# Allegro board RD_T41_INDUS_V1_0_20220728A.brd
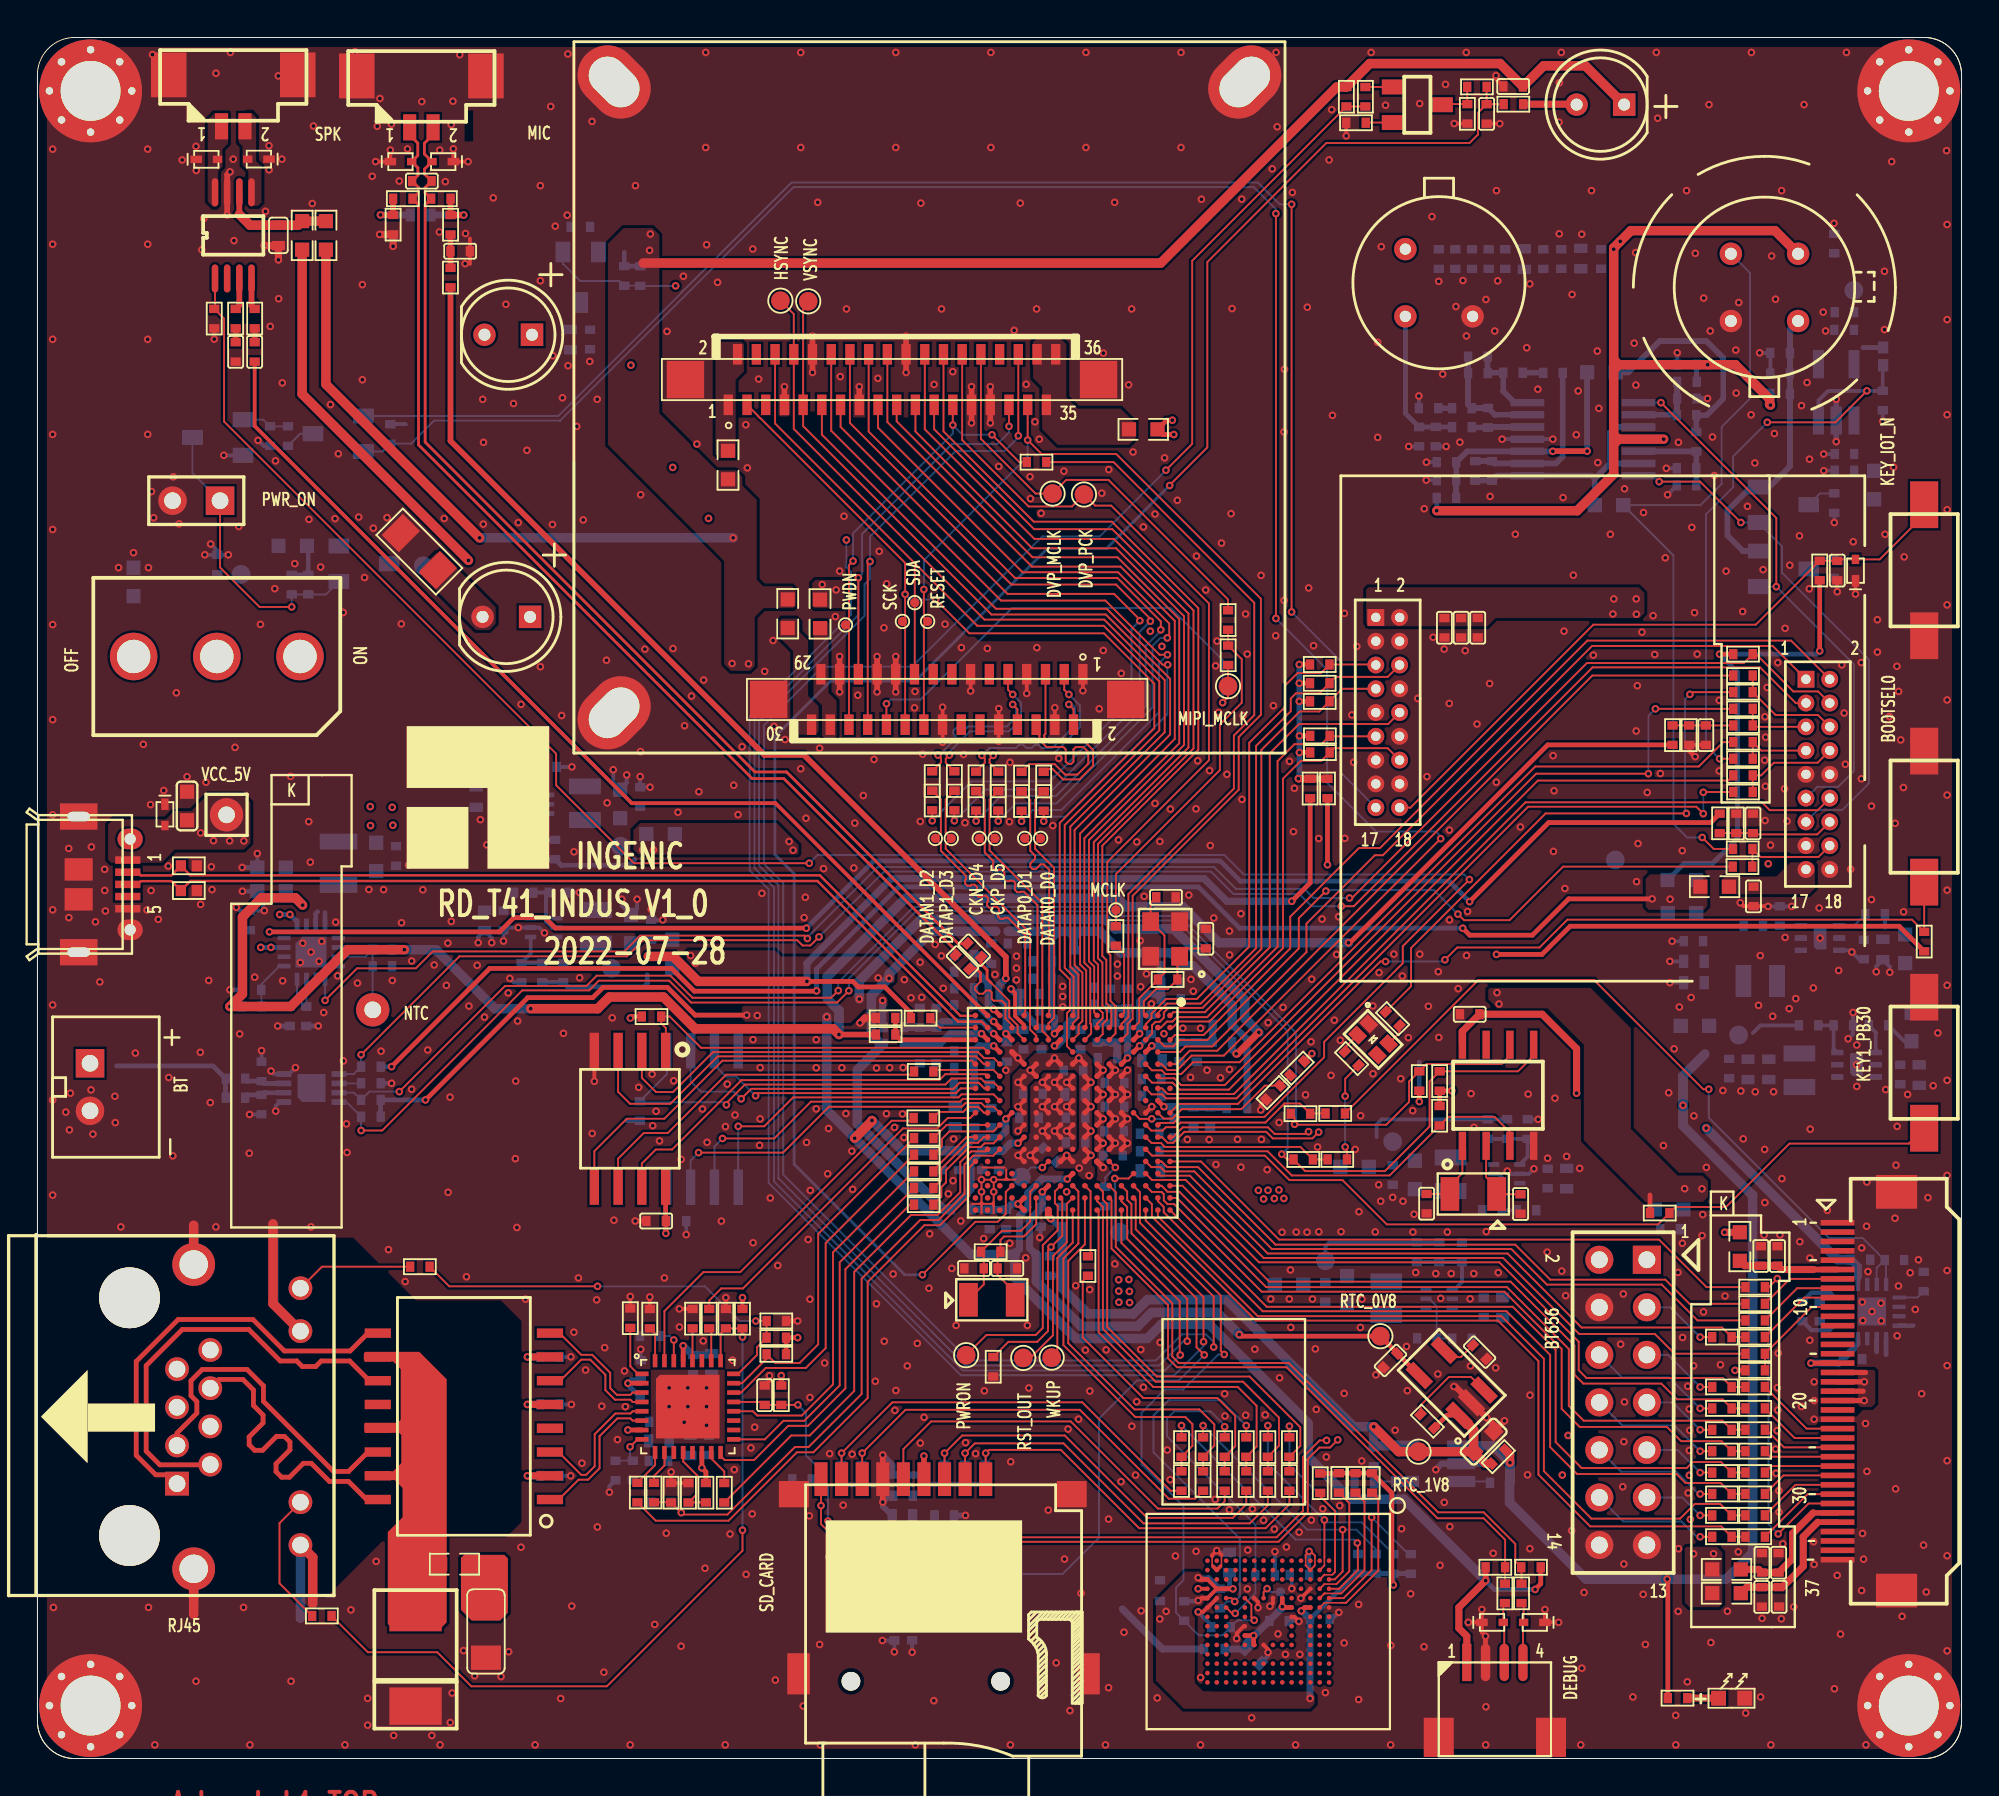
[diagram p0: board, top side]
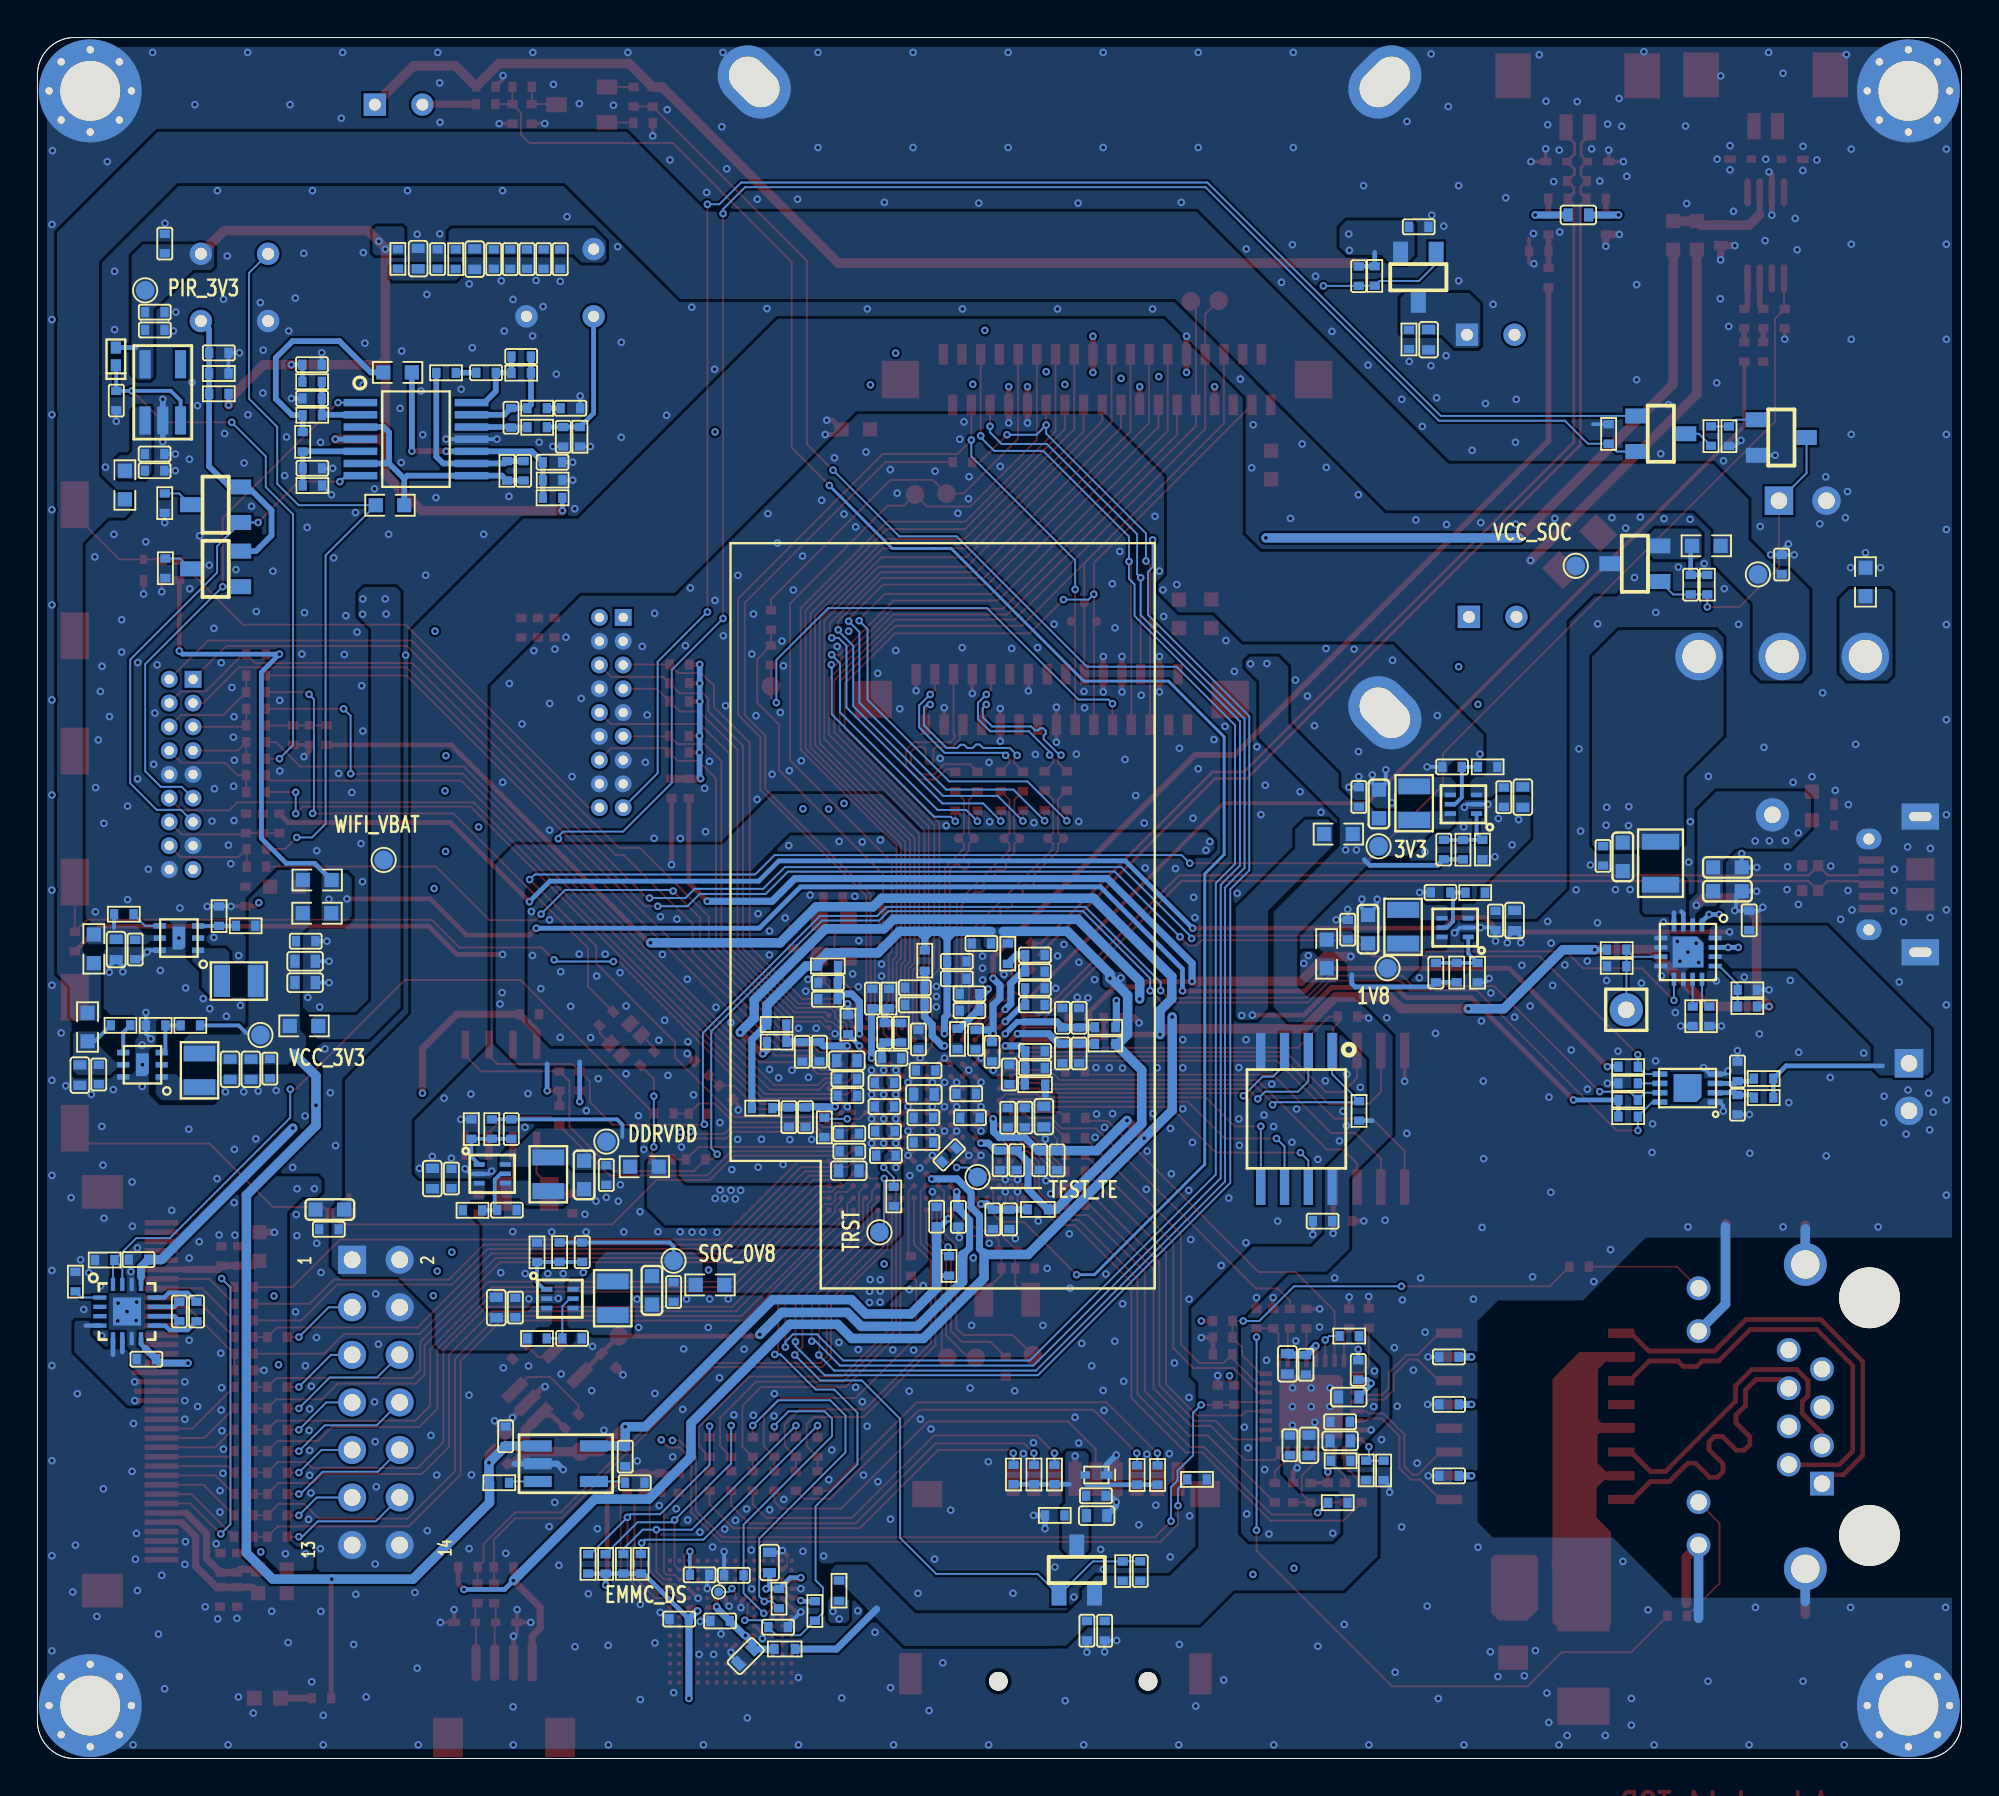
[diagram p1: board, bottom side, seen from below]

Outline 102.82 x 91.95 mm; copper layers: TOP, L2_GND, L3_PWR, BOTTOM. Coordinates in mm from the lower left corner of the outline.
Outline path: 0,89.95 0,2 ; 0,89.95 arc(0.59,91.36) 2,91.95 ; 0,89.95 0,2 ; 0,2 arc(0.59,0.59) 2,0 ; 0,2 arc(0.59,0.59) 2,0 ; 2,91.95 100.82,91.95 ; 2,91.95 100.82,91.95 ; 100.82,91.95 arc(102.24,91.36) 102.82,89.95 ; 100.82,91.95 arc(102.24,91.36) 102.82,89.95 ; 2,0 100.82,0 ; 2,0 100.82,0 ; 100.82,0 arc(102.24,0.59) 102.82,2 ; 100.82,0 arc(102.24,0.59) 102.82,2 ; 102.82,89.95 102.82,2 ; 102.82,89.95 102.82,2

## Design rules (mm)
net group CSI_CLKN_DVP_D4: nets CSI_CLKN_DVP_D4 MIPI_RX_2LANE_CLKN0
net group CSI_CLKP_DVP_D5: nets CSI_CLKP_DVP_D5 MIPI_RX_2LANE_CLKP0
net group CSI_DATAN0_DVP_D0: nets CSI_DATAN0_DVP_D0 MIPI_RX_2LANE_DN0
net group CSI_DATAN1_DVP_D2: nets CSI_DATAN1_DVP_D2 MIPI_RX_2LANE_DN1
net group CSI_DATAP0_DVP_D1: nets CSI_DATAP0_DVP_D1 MIPI_RX_2LANE_DP0
net group CSI_DATAP1_DVP_D3: nets CSI_DATAP1_DVP_D3 MIPI_RX_2LANE_DP1
net group MDI_RX: nets RX_N1 RX_P1
net group MDI_TX: nets TX_N0 TX_P0
net group MICNL: nets MICNL N16981743
net group MICPL: nets MICPL N16981740
net group RJ45_RX: nets RX+ RX-
net group RJ45_TX: nets TX+ TX-
net group USB: nets USB_DM0 USB_DP0
net group POWER: nets ADC_AVDD CODEC_AVDD CSI_VCC08 CSI_VCC18 DDR_VREF DDRPLL_VCCA EMMC_3V3 MICBIAS N16981952 PLL_AVDD18 RTC_0V8 RTC_1V8 SLCD_IOVDD SLCD_LEDA USB_AVD08 USB_AVD18 USB_AVD33 USB_VBUS VCM VOUT
nets with their own width: min track width 0.203; nets GND VCC_3V3

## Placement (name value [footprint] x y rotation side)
BT1  CON2 2.54mm LC  [CON2-2D54-LC]  2.81 35.87 270 top
C1  1uF/10V  [C0402]  9.61 63.79 90 bottom
C2  22uF/10V-0603  [C0603]  8 50.89 90 top
C3  22uF/10V-0603  [C0603]  18.11 48.17 270 bottom
C4  10nF/6.3V  [C0402]  19.16 48.22 270 bottom
C5  100nF/10V  [C0402]  91.67 49.96 90 top
C6  10uF/10V-0603  [C0603]  12.51 47.61 180 bottom
C7  10uF/10V-0603  [C0603]  12.51 46.34 180 bottom
C8  1uF/10V  [C0402]  11.35 44.78 90 bottom
C9  100nF/10V  [C0402]  89.16 54.67 270 top
C10  10uF/6.3V  [C0402_E]  98.62 43.22 270 bottom
C11  100nF/10V  [C0402]  97.6 43.22 270 bottom
C12  10uF/6.3V  [C0402_E]  88.52 42.59 180 bottom
C13  100nF/10V  [C0402]  88.49 43.67 180 bottom
C14  10uF/6.3V  [C0402_E]  88.52 41.45 180 bottom
C15  100nF/10V  [C0402]  14.48 62.71 270 bottom
C16  10uF/6.3V  [C0402_E]  23.45 51.36 270 bottom
C17  100nF/10V  [C0402]  24.46 51.36 270 bottom
C18  22uF/10V-0603  [C0603]  31.14 51 90 bottom
C19  100nF/10V  [C0402]  32.21 51.37 90 bottom
C20  10uF/6.3V  [C0402_E]  23.89 44.77 270 bottom
C21  100nF/10V  [C0402]  24.91 44.77 270 bottom
C22  22uF/10V-0603  [C0603]  31.72 44.31 90 bottom
C23  100nF/10V  [C0402]  32.8 44.28 90 bottom
C24  22pF/50V  [C0402]  27.67 48.56 90 bottom
C25  22pF/50V  [C0402]  28.09 41.99 90 bottom
C26  10uF/6.3V  [C0402_E]  81.72 30.99 90 bottom
C27  100nF/10V  [C0402]  80.7 30.99 90 bottom
C28  22uF/10V-0603  [C0603]  73.61 31.18 270 bottom
C29  100nF/10V  [C0402]  72.42 31.17 270 bottom
C30  10uF/6.3V  [C0402_E]  78.3 24.1 90 bottom
C31  100nF/10V  [C0402]  77.29 24.1 90 bottom
C32  22uF/10V-0603  [C0603]  69.99 25.01 270 bottom
C33  100nF/10V  [C0402]  68.83 24.92 270 bottom
C34  22pF/50V  [C0402]  77.5 33.63 270 bottom
C35  22pF/50V  [C0402]  73.71 27.05 270 bottom
C36  1uF/10V  [C0402]  11.98 34.93 270 bottom
C37  10uF/6.3V  [C0402_E]  59.47 31.4 0 bottom
C38  100nF/6.3V  [C0402]  59.44 33.38 0 bottom
C39  100nF/6.3V  [C0402]  59.44 32.44 0 bottom
C40  100nF/6.3V  [C0402]  59.54 35.41 0 bottom
C41  10nF/6.3V  [C0402]  59.54 36.3 0 bottom
C42  100nF/6.3V  [C0402]  57.55 38.78 90 bottom
C43  100nF/6.3V  [C0402]  58.21 40.6 90 bottom
C44  1uF/6.3V  [C0402]  57.18 37.42 180 bottom
C45  1uF/10V  [C0402]  11.98 36.71 90 bottom
C46  10uF/6.3V  [C0402_E]  49.04 34.29 270 bottom
C47  10uF/6.3V  [C0402_E]  55.45 35.48 180 bottom
C48  100nF/6.3V  [C0402]  54.1 32.25 135 bottom
C49  100nF/6.3V  [C0402]  55.48 34.24 180 bottom
C50  100nF/6.3V  [C0402]  55.74 38.42 90 bottom
C51  100nF/6.3V  [C0402]  52.99 34.24 0 bottom
C52  100nF/6.3V  [C0402]  50.89 36.55 90 bottom
C53  100nF/6.3V  [C0402]  50.07 34.25 270 bottom
C54  10nF/6.3V  [C0402]  55.48 32.92 180 bottom
C55  10nF/6.3V  [C0402]  55.36 36.76 180 bottom
C56  10nF/6.3V  [C0402]  53.19 35.52 0 bottom
C57  10nF/6.3V  [C0402]  50.97 34.24 270 bottom
C58  10uF/6.3V  [C0402_E]  59.57 37.28 0 bottom
C59  1uF/6.3V  [C0402]  60.58 41.45 0 bottom
C60  100nF/6.3V  [C0402]  60.58 40.56 0 bottom
C61  100nF/25V  [C0402]  49.52 42.93 180 bottom
C62  4.7uF/6.3V  [C0402]  49.52 42.04 180 bottom
C63  4.7uF/6.3V  [C0402]  52.38 43.54 0 bottom
C64  100nF/25V  [C0402]  50.06 43.18 135 top
C65  100nF/25V  [C0402]  49.44 42.56 135 top
C66  12pF/50V  [C0402]  62.44 43.8 270 top
C67  12pF/50V  [C0402]  60.31 46.01 180 top
C68  4.7uF/6.3V  [C0402]  49.52 40.26 180 bottom
C69  100nF/25V  [C0402]  49.52 41.15 180 bottom
C70  100nF/25V  [C0402]  33.06 28.72 0 top
C71  18pF/50V  [C0402]  51.83 26.19 180 top
C72  18pF/50V  [C0402]  50.05 26.19 0 top
C73  1uF/6.3V  [C0402]  50.88 28.8 270 bottom
C74  100nF/6.3V  [C0402]  51.77 28.8 270 bottom
C75  3.3nF/50V  [C0402]  10.59 75.15 270 top
C76  3.3nF/50V  [C0402]  11.61 75.15 270 top
C77  10uF/6.3V  [C0402_E]  12.88 81.37 270 top
C78  100pF/50V  [C0402]  20.54 84.27 0 top
C79  10uF/6.3V  [C0402_E]  20.48 82.46 0 bottom
C80  4.7uF/6.3V  [C0402]  46.74 6.83 270 bottom
C81  100nF/25V  [C0402]  45.79 6.83 270 bottom
C82  100nF/6.3V  [C0402]  43.89 10.02 90 bottom
C83  10uF/6.3V  [C0402_E]  46.22 12.98 180 bottom
C84  100nF/25V  [C0402]  46.26 14.04 180 bottom
C85  4.7uF/6.3V  [C0402]  22.59 80.53 0 top
C86  1uF/6.3V  [C0402]  77.8 17.22 90 bottom
C87  10uF/6.3V  [C0402_E]  64.97 5.47 315 bottom
C88  100nF/6.3V  [C0402]  66.35 7.35 0 bottom
C89  10uF/6.3V  [C0402_E]  63.7 10.48 90 bottom
C90  100nF/6.3V  [C0402]  68.53 7.45 0 bottom
C91  8.2pF/50V  [C0402]  65.61 9.79 0 bottom
C92  1uF/6.3V  [C0402]  63.25 7.02 180 bottom
C93  1uF/6.3V  [C0402]  67.44 9.82 180 bottom
C94  1uF/6.3V  [C0402]  71.41 16.13 270 bottom
C95  100nF/6.3V  [C0402]  96.18 63.47 90 top
C96  100nF/10V  [C0402]  27.23 52.98 0 bottom
C97  10nF/6.3V  [C0402]  70.91 14.74 180 bottom
C98  10uF/6.3V-0603  [C0603]  77.29 16.93 45 top
C99  1uF/6.3V  [C0402]  72.3 21.27 225 top
C100  10nF/6.3V  [C0402]  77.07 21.72 315 top
C101  100nF/6.3V  [C0402]  29.01 81.83 180 bottom
C102  100nF/6.3V  [C0402]  32.22 79.2 270 bottom
C103  1uF/6.3V  [C0402]  92.99 26.85 90 top
C104  100nF/6.3V  [C0402]  92.1 26.85 90 top
C105  1uF/6.3V  [C0402]  92.16 10.46 90 top
C106  100nF/6.3V  [C0402]  93.05 10.46 90 top
C107  10uF/6.3V  [C0402_E]  28.48 75.8 270 bottom
C108  100nF/10V  [C0402]  74.25 22.45 180 bottom
C109  10uF/10V-0603  [C0603]  87.2 29.33 0 bottom
C110  1uF/10V  [C0402]  87.25 28.27 0 bottom
C111  100nF/6.3V  [C0402]  76.97 60.41 270 top
C112  100nF/6.3V  [C0402]  76.08 60.41 270 top
C113  4.7uF/6.3V  [C0402]  75.19 60.41 270 top
C114  100nF/25V  [C0402]  91.71 46.06 270 top
C116  10uF/6.3V  [C0402_E]  34.88 16.74 90 bottom
C117  100nF/6.3V  [C0402]  35.89 16.74 90 bottom
C118  10uF/6.3V  [C0402_E]  32.75 19.31 0 bottom
C119  100nF/6.3V  [C0402]  32.24 20.76 90 bottom
C120  100nF/6.3V  [C0402]  78.86 89.33 180 top
C121  100nF/10V  [C0402]  96.56 69.69 180 bottom
C122  1uF/10V  [C0402]  96.56 68.8 180 bottom
C123  1uF/10V  [C0402]  96.55 76.32 180 bottom
C124  100nF/10V  [C0402]  96.56 77.27 180 bottom
C125  100nF/6.3V  [C0402]  77.44 87.86 270 top
C126  100nF/10V  [C0402]  98.61 72.55 270 bottom
C127  100nF/6.3V  [C0402]  88.15 74.46 180 bottom
C128  10uF/6.3V  [C0402_E]  82.48 80.13 90 bottom
C129  100nF/6.3V  [C0402]  57.56 36.1 180 bottom
C130  100nF/6.3V  [C0402]  57.49 32.21 180 bottom
C131  100nF/6.3V  [C0402]  57.54 33.51 180 bottom
C132  10nF/6.3V  [C0402]  57.56 34.83 180 bottom
C133  1uF/6.3V  [C0402]  61.78 34.27 270 bottom
C134  100nF/6.3V  [C0402]  62.67 34.27 270 bottom
C135  1uF/6.3V  [C0402]  49.51 36.89 180 bottom
C136  100nF/6.3V  [C0402]  49.51 37.78 180 bottom
C137  1uF/6.3V  [C0402]  47.16 37.67 270 bottom
C138  100nF/6.3V  [C0402]  48.05 37.67 270 bottom
C139  1uF/6.3V  [C0402]  47.16 39.58 90 bottom
C140  100nF/6.3V  [C0402]  48.05 39.58 90 bottom
C141  4.7uF/6.3V  [C0402]  51.81 37.76 270 bottom
C142  100nF/6.3V  [C0402]  52.69 38.41 270 bottom
C143  100nF/6.3V  [C0402]  53.61 28.94 270 bottom
C144  1uF/6.3V  [C0402]  55.94 40.27 0 bottom
C145  100nF/6.3V  [C0402]  55.94 41.18 0 bottom
C146  1uF/6.3V  [C0402]  53.02 39.96 0 bottom
C147  100nF/6.3V  [C0402]  53.02 40.85 0 bottom
C148  100nF/6.3V  [C0402]  34.15 28.71 180 bottom
C149  10uF/6.3V  [C0402_E]  36.03 21.09 270 bottom
C150  100nF/6.3V  [C0402]  35.04 21.04 270 bottom
C151  100nF/6.3V  [C0402]  38.86 19.41 90 top
C152  10uF/6.3V  [C0402_E]  33.21 16.97 0 bottom
C153  100nF/6.3V  [C0402]  33.21 17.99 0 bottom
C154  100nF/6.3V  [C0402]  27.39 15.1 180 bottom
C155  100nF/6.3V  [C0402]  27.39 18.92 180 bottom
C156  100nF/6.3V  [C0402]  27.4 21.46 180 bottom
C157  1nF/2KV-1206  [C1206]  23.97 6.79 90 top
C158  18pF/50V  [C0402]  74.24 29.65 90 top
C159  18pF/50V  [C0402]  79.26 29.63 90 top
C164  10uF/6.3V  [C0402_E]  100.56 36.51 270 bottom
C165  100nF/10V  [C0402]  99.55 36.54 270 bottom
C166  10uF/6.3V  [C0402_E]  91.41 36.82 270 bottom
C167  100nF/10V  [C0402]  90.4 36.86 270 bottom
C168  10uF/6.3V  [C0402_E]  92.53 36.82 270 bottom
C169  100nF/6.3V  [C0402]  54.77 28.95 90 bottom
C170  1uF/6.3V  [C0402]  48.34 31.96 270 bottom
C171  100nF/6.3V  [C0402]  49.26 31.96 270 bottom
C172  1uF/6.3V  [C0402]  61.03 37.76 270 bottom
C173  100nF/6.3V  [C0402]  61.95 37.75 270 bottom
C174  1uF/6.3V  [C0402]  53.69 42.59 180 bottom
C175  100nF/6.3V  [C0402]  53.69 41.66 180 bottom
C176  1uF/6.3V  [C0402]  50.49 31.96 270 bottom
C177  100nF/6.3V  [C0402]  51.38 31.96 270 bottom
C179  1uF/6.3V  [C0402]  93.07 8.64 270 top
C180  100nF/6.3V  [C0402]  92.15 8.64 270 top
C181  100nF/6.3V  [C0402]  76.54 39.76 180 top
C182  470nF/16V  [C0402]  94.32 23.88 270 bottom
C183  470nF/16V  [C0402]  95.24 23.89 270 bottom
C184  1uF/16V  [C0402]  97.42 26.66 180 bottom
C185  1uF/16V  [C0402]  97 21.33 180 bottom
C187  100nF/6.3V  [C0402]  81.44 80.11 90 bottom
C188  10uF/6.3V  [C0402_E]  79.46 80.1 270 bottom
C189  1uF/6.3V  [C0402]  78.44 80.11 270 bottom
C190  470nF/25V  [C0402]  77.55 80.11 270 bottom
C191  10nF/25V  [C0402]  76.66 80.11 270 bottom
C192  1nF/50V  [C0402]  75.78 80.11 270 bottom
C193  220pF/50V  [C0402]  74.89 80.11 270 bottom
C194  100nF/6.3V  [C0402]  88.15 72.66 0 bottom
C195  10nF/6.3V  [C0402]  76.84 68.8 270 bottom
C196  100nF/6.3V  [C0402]  96.02 80.93 90 bottom
C197  4.7uF/6.3V  [C0402]  78.85 74.04 0 bottom
C198  100nF/6.3V  [C0402]  74.72 70.62 270 bottom
C199  10nF/6.3V  [C0402]  77.52 71.63 90 bottom
C200  10nF/6.3V  [C0402]  76.97 74.91 0 bottom
C201  100nF/6.3V  [C0402]  75.3 69.26 180 bottom
C202  4.7uF/6.3V  [C0402]  74.34 72.14 180 bottom
C203  100nF/6.3V  [C0402]  88.13 68.93 180 bottom
C204  100nF/6.3V  [C0402]  93.13 75.1 180 bottom
C205  100nF/10V  [C0402]  27.84 46.27 0 bottom
C206  100nF/10V  [C0402]  77.74 29.3 180 bottom
D1  LXES1UTAA1-157  [DFN1006]  8.09 46.37 0 top
D2  LXES1UTAA1-157  [DFN1006]  8.09 47.69 0 top
D3  ESD5451X  [ESD0402]  6.81 50.45 270 top
D4  ESD5451X  [ESD0402]  80.02 7.28 180 top
D5  ESD5451X  [ESD0402]  77.73 7.28 0 top
D6  ESD5451X  [ESD0402]  11.84 85.45 180 top
D7  ESD5451X  [ESD0402]  9.02 85.44 0 top
D8  ESD5451X  [ESD0402]  46.23 15.15 0 bottom
D9  ESD5451X  [ESD0402]  21.69 85.31 180 top
D10  ESD5451X  [ESD0402]  97.16 63.46 90 top
D11  LED RGB CC  [D0603_LED3_CC]  71.38 38.42 135 top
D12  BAT54C  [SOT23]  16.07 70.78 270 bottom
D13  LED Red  [D0603_LED]  90.54 3.22 0 top
D14  940nm IRLED  [DIP2_2D54_LED]  25.16 76.06 180 top
D15  ESD5451X  [ESD0402]  19.4 85.31 0 top
D16  940nm IRLED  [DIP2_2D54_LED]  25.06 60.99 180 top
D17  P3100SC  [SMB]  20.21 5.3 90 top
D18  RB521CS-30  [SOD923_RB521CS-30]  98.63 74.9 270 bottom
FB1  220ohm/1.4A  [FB0402]  62.89 5.85 0 bottom
FB2  1000ohm/250mA  [FB0402]  64.1 34.75 0 bottom
FB3  1000ohm/250mA  [FB0402]  60.58 42.34 0 bottom
FB4  1000ohm/250mA  [FB0402]  49.51 36.01 0 bottom
FB5  1000ohm/250mA  [FB0402]  45.76 38.18 0 bottom
FB6  1000ohm/250mA  [FB0402]  45.76 39.07 0 bottom
FB7  1000ohm/250mA  [FB0402]  49.36 29.34 0 bottom
FB8  1000ohm/250mA  [FB0402]  50.97 43 270 bottom
FB9  1000ohm/250mA  [FB0402]  53.66 38.45 270 bottom
FB10  1000ohm/250mA  [FB0402]  55.41 42.63 90 bottom
FB11  220ohm/1.4A  [FB0402]  59.99 8.97 270 bottom
H1  MHOBL  [MHOLE_3D0X2D0]  30.82 89.57 270 top
H2  MHOBL  [MHOLE_3D0X2D0]  64.52 89.57 0 top
H3  MHOBL  [MHOLE_3D0X2D0]  30.82 55.87 0 top
J1  SW3 4.45mm  [PSW_3P]  9.59 58.88 270 top
J2  MICRO USB  [MICROUSB_B_NJ5P]  4.83 46.7 90 top
J3  HEADER2 2.54mm  [SIP2M_2D54]  8.49 67.2 180 top
J4  CON4 1.0mm WT  [CON4-1D0-WT]  77.89 2.64 0 top
J5  CON2 1.25mm LT  [CON2-1D25-LT]  10.47 89.4 180 top
J6  MICROSD_TF  [TFCARD]  48.42 14.73 0 top
J7  CON2 1.25mm LT  [CON2-1D25-LT]  20.52 89.35 180 top
J9  HEADER18 1.27mm Male  [HEADER9X2M_1D27]  72.16 55.88 90 top
J10  CON36 0.5mm LT  [FPC-CON36-0D5-LT]  45.67 73.67 0 top
J11  CON30 0.5mm LT  [FPC-CON30-0D5-LT]  48.62 56.58 180 top
J12  HEADER14 2.54mm MALE  [HEADER7X2M_2D54]  84.74 19.03 270 top
J13  RJ45 With Led  [RJ45-LED-1A]  -0.21 18.27 270 top
J14  HEADER18 1.27mm Male  [HEADER9X2M_1D27]  95.15 52.58 90 top
J15  CON37 0.5mm QCHX  [LCD_CON37_0D5_WTXG_MTF28]  99.2 19.63 90 top
L1  2.2uH/2.2A-2520  [L2520]  16.09 47.83 90 bottom
L2  2.2uH/1.5A-2016  [L2016]  92.06 41.54 0 bottom
L3  1uH/2.7A  [L2016]  29.25 51.04 90 bottom
L4  1uH/2.7A  [L2016]  29.85 44.44 90 bottom
L5  1uH/2.7A  [L2016]  75.52 31.22 270 bottom
L6  1uH/2.7A  [L2016]  72.08 24.59 270 bottom
L8  2.2uH/1.5A-2016  [L2016]  94.16 36.77 270 bottom
NOREF  -  []  4.32 233.9 0 top
NOREF#2  -  []  -98.17 -124.02 0 top
NOREF#3  -  []  85.84 253.93 0 top
NOREF#4  -  []  0 89.95 0 top
NOREF#5  -  []  2 0 90 top
NOREF#6  -  []  23.29 51.09 0 top
Q1  WPM3401  [SOT23]  17.46 63.83 90 bottom
Q2  MMBT3904  [SOT23]  9.63 70.58 270 bottom
Q3  WPM3401  [SOT23]  47.28 10.07 180 bottom
Q4  XYC-PTJZ5E550BC-IC-C  [PD2_2D54]  83.52 88.36 0 top
Q5  WNM2016  [SOT23]  73.74 88.35 270 top
Q6  WPM3401  [SOT23]  93.3 63.56 90 bottom
Q7  WPM3401  [SOT23]  93.3 66.99 90 bottom
Q8  WPM3401  [SOT23]  29.03 79.14 0 bottom
R1  300R-0603  [R0603]  5.13 62.86 270 bottom
R2  750K/1%  [R0402]  89.9 49.96 90 top
R3  499K/1%  [R0402]  90.79 49.96 270 top
R4  10K  [R0402]  11.45 40.18 180 bottom
R5  10K  [R0402]  11.45 41.07 180 bottom
R6  560R/1%  [R0402]  14.37 39.66 90 bottom
R7  2K/1%  [R0402]  13.48 39.66 90 bottom
R8  100K  [R0402]  91.14 59 180 top
R9  10K  [R0402]  18.43 43.21 0 bottom
R10  100K  [R0402]  87.38 54.67 270 top
R11  100K  [R0402]  18.43 42.32 180 bottom
R12  200K/1%  [R0402]  88.27 54.67 90 top
R13  0R-0603  [R0603]  88.58 39.14 0 bottom
R14  0R-0603  [R0603]  99.81 43.26 90 bottom
R15  100K  [R0402]  98.21 45.11 0 bottom
R16  1M/1%  [R0402]  91.7 44.49 180 bottom
R17  499K/1%  [R0402]  93.12 45.01 270 bottom
R18  0R-0603  [R0603]  13.64 64.79 0 bottom
R19  0R-0603  [R0603]  33.3 49.39 180 bottom
R20  0R-0603  [R0603]  33.93 42.99 90 bottom
R21  100K  [R0402]  13.59 62.71 270 bottom
R22  100K  [R0402]  25.33 52.98 0 bottom
R23  1M/1%  [R0402]  26.98 41.99 270 bottom
R24  10K/1%  [R0402]  45.33 38.68 180 top
R25  1M/1%  [R0402]  26.65 48.56 270 bottom
R26  100K  [R0402]  25.99 46.26 0 bottom
R27  15K/1%  [R0402]  45.33 39.57 180 top
R28  221K/1%  [R0402]  25.6 48.56 90 bottom
R29  499K/1%  [R0402]  25.87 41.99 90 bottom
R30  0R-0603  [R0603]  70.39 31.62 0 bottom
R31  0R-0603  [R0603]  66.88 25.3 0 bottom
R32  100K  [R0402]  79.58 29.29 180 bottom
R33  750K/1%  [R0402]  78.54 33.63 90 bottom
R34  100K  [R0402]  76.13 22.44 180 bottom
R35  249K/1%  [R0402]  74.92 27.05 90 bottom
R36  499K/1%  [R0402]  79.64 33.63 270 bottom
R37  750K/1%  [R0402]  76.13 27.04 270 bottom
R38  33R  [R0402]  57.63 43.94 270 top
R39  33R  [R0402]  56.14 26.31 270 top
R40  10K  [R0402]  17.82 34.3 180 bottom
R41  1M  [R0402]  60.4 41.62 0 top
R42  10K  [R0402]  77.91 10.22 180 top
R43  33R  [R0402]  47.36 36.7 0 top
R44  100K  [R0402]  32.82 39.64 180 top
R45  10K  [R0402]  79.82 10.22 0 top
R46  10K  [R0402]  17.82 35.19 180 bottom
R47  100K  [R0402]  17.82 36.96 180 bottom
R48  33R  [R0402]  78.42 8.82 90 top
R49  470R  [R0402]  10.58 35.31 180 bottom
R50  100R  [R0402]  10.58 36.33 180 bottom
R51  33R  [R0402]  79.31 8.82 90 top
R52  1M  [R0402]  50.94 27.07 0 top
R53  10K  [R0402]  17.82 36.07 0 bottom
R54  0R-0603  [R0603]  87.87 46.93 0 bottom
R55  1K  [R0402]  47.2 39.55 180 top
R56  0R-0603  [R0603]  14.15 81.37 270 top
R57  0R-0603  [R0603]  15.42 81.37 270 top
R58  100K  [R0402]  9.45 76.93 270 top
R59  68K/1%  [R0402]  10.59 76.93 270 top
R60  68K/1%  [R0402]  11.61 76.93 270 top
R61  100K  [R0402]  48.48 15.17 90 bottom
R62  100K  [R0402]  44.06 15.15 90 bottom
R63  100K  [R0402]  42.97 15.15 90 bottom
R64  100K  [R0402]  50.66 15.17 90 bottom
R65  100K  [R0402]  49.57 15.17 90 bottom
R66  100K  [R0402]  44.83 10.01 90 bottom
R67  1.1K  [R0402]  19.01 81.95 270 top
R68  100K  [R0402]  48.46 12.99 0 bottom
R69  1.1K  [R0402]  19.53 83.33 180 top
R70  10K  [R0402]  71.51 10.41 90 bottom
R71  10K  [R0402]  70.57 10.41 90 bottom
R72  10K  [R0402]  73.4 10.4 90 bottom
R73  10K  [R0402]  72.46 10.4 90 bottom
R74  10K  [R0402]  68.55 14.71 270 top
R75  10K  [R0402]  69.55 14.72 270 top
R76  10K  [R0402]  70.44 14.72 270 top
R77  10K  [R0402]  71.32 14.72 270 top
R78  10K  [R0402]  63.2 8.55 270 bottom
R79  100K  [R0402]  61.28 7.88 90 bottom
R80  1.1K  [R0402]  21.56 83.33 180 top
R81  1.1K  [R0402]  22.08 81.94 90 top
R82  0R  [R0402]  64.6 14.83 270 top
R83  0R  [R0402]  22.07 79.12 270 top
R84  0R  [R0402]  64.6 16.64 90 top
R85  0R  [R0402]  63.44 14.83 270 top
R86  0R  [R0402]  63.44 16.64 90 top
R87  0R  [R0402]  62.29 14.83 270 top
R88  10K  [R0402]  40.86 14.91 180 bottom
R89  100K  [R0402]  86.69 29.14 180 top
R90  100K  [R0402]  95.24 63.47 90 top
R91  1M/1%  [R0402]  96.51 39.17 0 bottom
R92  10K/1%  [R0402]  78.87 88.38 0 top
R93  0R-0603  [R0603]  87.88 45.16 0 bottom
R94  1K  [R0402]  70.23 37.4 135 top
R95  1K  [R0402]  72.42 39.53 315 top
R96  620K/1%  [R0402]  94.65 39.17 180 bottom
R97  0R  [R0402]  78.07 16.13 225 top
R98  0R  [R0402]  68.94 51.82 270 top
R99  0R-0603  [R0603]  36.9 69.1 270 top
R100  0R  [R0402]  52.59 52.2 90 top
R101  0R  [R0402]  52.59 51.16 270 top
R102  0R  [R0402]  53.78 52.2 90 top
R103  0R  [R0402]  53.78 51.16 270 top
R104  0R  [R0402]  49 52.22 90 top
R105  0R  [R0402]  49 51.18 270 top
R106  0R  [R0402]  47.82 52.22 90 top
R107  0R  [R0402]  47.82 51.18 270 top
R108  0R  [R0402]  51.34 52.21 90 top
R109  0R  [R0402]  51.34 51.17 270 top
R110  0R  [R0402]  50.16 52.21 90 top
R111  0R-0603  [R0603]  98.15 68.04 90 bottom
R112  100K  [R0402]  69.95 88.78 90 top
R113  0R  [R0402]  76.93 89.31 180 top
R114  100R  [R0402]  70.96 88.78 270 top
R115  100K/1%  [R0402]  76.41 87.87 90 top
R116  240R/1%  [R0402]  57.06 30.03 90 bottom
R117  240R/1%  [R0402]  60.77 33.72 90 bottom
R118  10K/1%  [R0402]  56.66 38.78 270 bottom
R119  10K/1%  [R0402]  57.32 40.6 270 bottom
R120  33R  [R0402]  59.51 39.21 270 bottom
R121  1K  [R0402]  54.11 26.32 90 bottom
R122  1K  [R0402]  51.08 20.93 90 top
R123  100K  [R0402]  32.2 34.6 270 bottom
R124  0R  [R0402]  50.16 51.17 270 top
R125  0R  [R0402]  63.63 58.94 270 top
R126  0R  [R0402]  63.63 60.82 90 top
R127  0R-0603  [R0603]  59.1 71.01 0 top
R128  0R-0603  [R0603]  41.82 61.15 270 top
R129  0R-0603  [R0603]  40.09 61.16 270 top
R130  0R  [R0402]  91.8 19.85 0 top
R131  0R  [R0402]  62.29 16.64 90 top
R132  0R  [R0402]  61.14 14.83 270 top
R133  0R  [R0402]  61.14 16.64 90 top
R134  0R  [R0402]  66.9 14.83 270 top
R135  0R  [R0402]  66.9 16.64 90 top
R136  0R  [R0402]  65.75 14.83 270 top
R137  0R  [R0402]  65.75 16.64 90 top
R138  0R  [R0402]  63.32 38.28 180 bottom
R139  0R  [R0402]  68.01 51.82 270 top
R140  4.7K  [R0402]  74.94 36.2 270 top
R141  10K  [R0402]  78.14 14.74 180 bottom
R142  100K  [R0402]  74.28 18.03 135 top
R143  0R  [R0402]  53.39 69.26 0 top
R144  0R  [R0402]  90.02 19.85 180 top
R145  0R  [R0402]  91.8 18.71 0 top
R146  0R  [R0402]  90.02 18.71 180 top
R147  0R-0603  [R0603]  90.26 10.1 0 top
R148  0R-0603  [R0603]  90.26 8.83 0 top
R149  0R  [R0402]  91.8 17.57 0 top
R150  0R  [R0402]  90.02 17.56 180 top
R151  0R-0603  [R0603]  90.97 27.35 270 top
R152  4.7K  [R0402]  73.85 36.2 270 top
R153  10K  [R0402]  74.93 34.34 90 top
R154  0R  [R0402]  91.8 16.42 0 top
R155  0R  [R0402]  90.02 16.42 180 top
R156  0R  [R0402]  91.8 15.28 0 top
R157  0R  [R0402]  91.8 20.74 180 top
R158  0R  [R0402]  90.02 15.28 180 top
R159  10R/1%-1206  [R1206]  20.41 64.48 135 top
R160  0R  [R0402]  91.8 14.14 0 top
R161  0R  [R0402]  90.02 14.13 180 top
R162  0R  [R0402]  91.8 12.99 0 top
R163  0R  [R0402]  90.02 12.99 180 top
R164  0R  [R0402]  91.8 11.85 0 top
R165  10K  [R0402]  31.36 79.21 90 bottom
R166  0R  [R0402]  90.02 11.85 180 top
R167  100K  [R0402]  29.53 75.81 270 bottom
R168  0R  [R0402]  91.8 22.52 0 top
R169  0R  [R0402]  90.02 22.52 180 top
R170  0R  [R0402]  91.8 25.19 0 top
R171  0R  [R0402]  91.8 24.3 0 top
R172  0R  [R0402]  91.8 23.41 0 top
R173  0R-0603  [R0603]  100.15 39.08 270 bottom
R174  0R  [R0402]  91.8 21.63 0 top
R175  33R  [R0402]  47.34 34.22 180 top
R176  0R  [R0402]  47.36 31.37 180 top
R177  0R  [R0402]  47.36 32.26 180 top
R178  0R  [R0402]  47.36 33.15 180 top
R179  33R  [R0402]  47.36 29.59 180 top
R180  33R  [R0402]  47.36 30.48 180 top
R181  0R  [R0402]  69.46 32.01 180 top
R182  0R  [R0402]  67.64 32.01 0 top
R183  0R  [R0402]  69.35 34.46 180 top
R184  0R  [R0402]  67.5 34.45 0 top
R185  0R  [R0402]  63.32 39.21 180 bottom
R186  0R-0603  [R0603]  89.63 46.58 180 top
R187  0R  [R0402]  91.14 56.08 0 top
R188  0R  [R0402]  91.14 55.19 0 top
R189  1.5K  [R0402]  39.49 21.6 180 top
R190  33R  [R0402]  36.7 14.2 90 top
R191  33R  [R0402]  35.9 23.5 270 top
R192  10K  [R0402]  33.34 13.67 0 bottom
R193  10K  [R0402]  33.86 14.2 90 top
R194  2.49K/1%  [R0402]  31.68 23.53 90 top
R195  33R  [R0402]  32.06 14.21 90 top
R196  10K  [R0402]  31.82 15.39 90 bottom
R197  10K  [R0402]  30.89 15.39 270 bottom
R198  33R  [R0402]  32.95 14.21 90 top
R199  10K  [R0402]  35.72 14.2 270 top
R200  10K  [R0402]  34.79 14.2 90 top
R201  10K  [R0402]  35.01 23.5 270 top
R202  10K  [R0402]  39.49 22.49 180 top
R203  10K  [R0402]  39.49 23.38 0 top
R204  0R  [R0402]  32.73 23.5 270 top
R205  10K  [R0402]  37.68 23.5 270 top
R206  10K  [R0402]  36.79 23.5 90 top
R207  10K  [R0402]  39.75 19.41 270 top
R208  100K  [R0402]  98.38 39.17 0 bottom
R209  10K  [R0402]  32.72 22.57 180 bottom
R210  0R  [R0402]  33.18 15.91 0 bottom
R211  300R  [R0402]  20.44 26.28 0 top
R212  10K  [R0402]  99.23 26.63 0 bottom
R213  0R  [R0402]  91.14 52.52 0 top
R214  7.68K/1%  [R0402]  100.8 25.48 90 bottom
R215  0R  [R0402]  91.14 51.64 0 top
R217  300R  [R0402]  15.2 7.62 0 top
R218  0R  [R0402]  91.14 54.3 0 top
R220  0R  [R0402]  91.14 53.41 0 top
R221  75R/1%-0603  [R0603]  22.28 10.39 180 top
R223  0R  [R0402]  91.14 57.86 0 top
R225  0R  [R0402]  91.14 56.97 0 top
R226  27K/1%  [R0402]  70.46 87.39 0 top
R227  15M/1%  [R0402]  88.15 73.55 0 bottom
R228  20K/1%  [R0402]  83.56 80.11 270 bottom
R229  0R  [R0402]  91.12 47.65 0 top
R230  0R  [R0402]  91.13 48.59 0 top
R231  1M  [R0402]  13.39 70.65 270 bottom
R232  1M  [R0402]  12.43 70.65 90 bottom
R233  4.7K  [R0402]  18.86 70.77 90 bottom
R234  1K  [R0402]  87.65 3.23 0 top
R246  100K  [R0402]  68.53 56.48 0 top
R247  100K  [R0402]  68.54 54.64 0 top
R248  100K  [R0402]  68.54 53.75 0 top
R249  100K  [R0402]  68.53 58.45 0 top
R250  100K  [R0402]  68.53 57.45 0 top
R252  499K/1%  [R0402]  80.47 80.1 90 bottom
R253  15M/1%  [R0402]  88.14 71.77 180 bottom
R254  10M/1%  [R0402]  77.73 68.79 270 bottom
R255  20K/1%  [R0402]  76.12 71.13 0 bottom
R256  100K/1%  [R0402]  80.99 74.03 180 bottom
R257  0R-0603  [R0603]  83.99 66.96 0 bottom
R258  15M/1%  [R0402]  75.3 67.35 180 bottom
R259  1M/1%  [R0402]  73.84 70.62 90 bottom
R260  10M/1%  [R0402]  76.97 74.01 0 bottom
R261  0R-0603  [R0603]  83.58 74.05 0 bottom
R262  15M/1%  [R0402]  75.29 68.3 0 bottom
R263  15M/1%  [R0402]  88.65 70.35 90 bottom
R264  100K/1%  [R0402]  76.12 72.14 0 bottom
R265  1M/1%  [R0402]  93.13 72.91 180 bottom
R266  15M/1%  [R0402]  88.13 68.01 0 bottom
R267  39K/1%  [R0402]  93.13 74 0 bottom
R268  39K/1%  [R0402]  95.99 63.59 90 bottom
R269  39K/1%  [R0402]  96.02 67.07 90 bottom
R270  100K  [R0402]  100.83 43.65 270 top
R271  100K  [R0402]  67.32 36.88 45 top
R272  100K  [R0402]  66.03 35.58 45 top
SW1  KEY2_SMD  [SW2_SMD]  100.83 37.17 270 top
SW2  KEY2_SMD  [SW2_SMD]  100.83 63.48 270 top
SW3  KEY2_SMD  [SW2_SMD]  100.83 50.32 270 top
T1  MechanicalHole  [MHOLE_5D5P3D2H]  2.84 2.83 0 top
T2  MechanicalHole  [MHOLE_5D5P3D2H]  100 2.83 0 top
T3  MechanicalHole  [MHOLE_5D5P3D2H]  100 89.09 0 top
T4  MechanicalHole  [MHOLE_5D5P3D2H]  2.84 89.09 0 top
TP1  D0.9mm_PTH  [TEST_HOLE]  10.11 50.42 180 top
TP2  1mm_SMD  [TEST_SMD]  10.88 63.26 90 bottom
TP3  D0.9mm_PTH  [TEST_HOLE]  17.92 40 270 bottom
TP4  1mm_SMD  [TEST_SMD]  84.32 48.01 90 bottom
TP5  1mm_SMD  [TEST_SMD]  20.62 63.72 0 bottom
TP6  1mm_SMD  [TEST_SMD]  31.15 48.74 270 bottom
TP7  1mm_SMD  [TEST_SMD]  30.68 42.22 270 bottom
TP8  1mm_SMD  [TEST_SMD]  72.42 32.96 90 bottom
TP9  1mm_SMD  [TEST_SMD]  68.83 26.59 90 bottom
TP10  1mm_SMD  [TEST_SMD]  54.25 67.58 270 top
TP11  1mm_SMD  [TEST_SMD]  97.07 78.44 180 bottom
TP12  1mm_SMD  [TEST_SMD]  49.63 21.55 90 top
TP13  1mm_SMD  [TEST_SMD]  54.2 21.42 270 top
TP14  1mm_SMD  [TEST_SMD]  52.68 21.4 270 top
TP15  1mm_SMD  [TEST_SMD]  57.83 28.11 270 bottom
TP16  1mm_SMD  [TEST_SMD]  52.59 31.07 270 bottom
TP18  0.5mm_SMD  [TEST_SMD_0D5]  52.76 49.16 180 top
TP19  1mm_SMD  [TEST_SMD]  55.93 67.53 180 top
TP20  1mm_SMD  [TEST_SMD]  39.7 77.88 0 top
TP21  0.5mm_SMD  [TEST_SMD_0D5]  53.61 49.16 0 top
TP22  1mm_SMD  [TEST_SMD]  41.19 77.85 90 top
TP23  0.5mm_SMD  [TEST_SMD_0D5]  48.83 49.16 0 top
TP24  0.5mm_SMD  [TEST_SMD_0D5]  47.98 49.16 90 top
TP25  0.5mm_SMD  [TEST_SMD_0D5]  51.17 49.16 0 top
TP26  0.5mm_SMD  [TEST_SMD_0D5]  50.33 49.16 0 top
TP27  0.5mm_SMD  [TEST_SMD_0D5]  57.63 45.34 0 top
TP28  0.5mm_SMD  [TEST_SMD_0D5]  46.88 61.75 180 top
TP29  0.5mm_SMD  [TEST_SMD_0D5]  46.23 60.75 180 top
TP30  0.5mm_SMD  [TEST_SMD_0D5]  47.57 60.75 270 top
TP31  0.5mm_SMD  [TEST_SMD_0D5]  43.18 60.56 180 top
TP32  1mm_SMD  [TEST_SMD]  63.62 57.29 0 top
TP33  0.5mm_SMD  [TEST_SMD_0D5]  66.42 8.9 0 bottom
TP34  1mm_SMD  [TEST_SMD]  71.76 22.57 135 top
TP35  1mm_SMD  [TEST_SMD]  90.91 38.65 0 bottom
TP36  1mm_SMD  [TEST_SMD]  73.81 16.4 0 top
U1  ETA6003Q3Q  [DFN16_0D5_ETA6003]  14.62 43.09 270 bottom
U2  ETA3425D2G  [DFN6_0D65_ETA3425]  95.26 43.83 0 bottom
U3  MP1601GTF-18  [SOT563]  26.62 50.98 90 bottom
U4  MP1601GTF-18  [SOT563]  27.06 44.39 90 bottom
U5  MP1601GTF-18  [SOT563]  78.52 31.24 270 bottom
U6  ETA3425D2G  [DFN6_0D65_ETA3425]  97.21 37.07 0 bottom
U7  T41 BGA232  [BGA232_0D65_T41]  55.33 34.5 270 top
U8  MX25L12833F  [WSOP8_1D27]  31.67 34.18 270 top
U9  CW2015CHBD  [QFN8_0D5_CW2015]  14.64 35.82 90 bottom
U10  CS8302M  [MSOP8_0D65]  10.47 81.37 0 top
U11  FEMDNN008G-08A39  [BGA153_0D5_FEMDNN008G]  65.77 7.32 270 top
U12  SGM2019-1.8YN5G  [SOT23-5]  74.59 15.75 270 bottom
U13  SGM2036-0.8YN5G  [SOT23-5]  75.58 20.07 45 top
U14  MP1605GTF  [SOT563]  74.91 24.57 270 bottom
U15  S-1339D33  [SOT23-5]  96.13 72.99 180 bottom
U16  XYC-PIR203CJZ-S0  [DIP3_PIR]  74.9 78.84 315 top
U18  MX25L12833F  [WSOP8_1D27]  35.55 34.17 270 bottom
U19  SZ18201  [QFN32_0D5_SZ18201]  34.76 18.8 0 top
U20  FC1680C  [QFP16_1D27]  22.79 18.28 180 top
U21  BM8563ESA  [SOP8_1D27_BM8563]  78.05 35.44 0 top
U23  SGM3124  [TQFN16_0D5_SGM3124]  98.04 23.88 180 bottom
U24  SGM8044  [TSSOP14_0D65_SGM8044]  82.6 70.49 180 bottom
U25  P904B-S  [DIP4_P904B_S]  92.29 78.59 135 top
Y1  24M  [CRY_2D5X2D0]  60.27 43.79 90 top
Y2  32.768KHz  [CRY_3D2X1D5]  76.73 30.16 180 top
Y3  32.768KHz  [CRY_3D2X1D5]  51 24.51 0 top

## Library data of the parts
BT1 = BATTERY
C1-C63 C66-C114 C116-C159 C164-C177 C179-C185 C187-C206 = CAP
C64 C65 = CAP: signal model: CAP_C0402_100NF/25V_100nF/25V
D1-D10 D15 = ESD
D11 = LED_3C
D12 = DIODE_CA3
D13 D14 D16 = LED_1
D17 = P3100
D18 = DIODE
FB1-FB11 = BEAD
H1-H3 = MHOLE1
J1 = SW3
J2 = MICROUSB_0
J3 = HEADER2X1
J4 = CON_4X1
J5 J7 = CON_2X1
J6 = MMC_SD
J9 J14 = HEADER_9X2
J10 = FPCCON_18X2
J11 = FPCCON_15x2
J12 = HEADER_7x2
J13 = RJ45_1x1_LED
J15 = MTF0280QT-30
L1-L6 L8 = INDUCTOR
Q1 Q3 Q6-Q8 = P_MOS
Q2 = NPN
Q4 = PHOTO_DIODE
Q5 = N_MOS
R1-R99 R101 R103 R105 R107 R109 R111-R215 R217 R218 R220 R221 R223 R225-R234 R246-R250 R252-R272 = RES
R100 R102 R104 R106 R108 R110 = RES: signal model: RES_R0402_0R_0R
SW1-SW3 = PUSHBUTTON
T1-T4 = MHOLE2
TP1-TP16 TP18-TP36 = TP
U1 = ETA6003
U2 U6 = ETA3425
U3-U5 U14 = MP160x
U7 = T41_BGA232
U8 U18 = SPI_NOR
U9 = CW2015
U10 = CS8302
U11 = FEMDNN008G
U12 U15 = SGM2019
U13 = SGM2036
U16 = PIR
U19 = SZ18201
U20 = FC1680C
U21 = BM8563
U23 = SGM3124
U24 = OPAMP_4
U25 = PIR_4
Y1 = XTAL_P4
Y2 Y3 = XTAL_P2

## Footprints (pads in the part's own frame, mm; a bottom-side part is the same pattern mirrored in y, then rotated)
BGA153_0D5_FEMDNN008G
  round 0.249 smd: A1(-3.25,3.25) A2(-2.75,3.25) A3(-2.25,3.25) A4(-1.75,3.25) A5(-1.25,3.25) A6(-0.75,3.25) A7(-0.25,3.25) A8(0.25,3.25) A9(0.75,3.25) A10(1.25,3.25) A11(1.75,3.25) A12(2.25,3.25) A13(2.75,3.25) A14(3.25,3.25) B1(-3.25,2.75) B2(-2.75,2.75) B3(-2.25,2.75) B4(-1.75,2.75) B5(-1.25,2.75) B6(-0.75,2.75) B7(-0.25,2.75) B8(0.25,2.75) B9(0.75,2.75) B10(1.25,2.75) B11(1.75,2.75) B12(2.25,2.75) B13(2.75,2.75) B14(3.25,2.75) C1(-3.25,2.25) C2(-2.75,2.25) C3(-2.25,2.25) C4(-1.75,2.25) C5(-1.25,2.25) C6(-0.75,2.25) C7(-0.25,2.25) C8(0.25,2.25) C9(0.75,2.25) C10(1.25,2.25) C11(1.75,2.25) C12(2.25,2.25) C13(2.75,2.25) C14(3.25,2.25) D1(-3.25,1.75) D2(-2.75,1.75) D3(-2.25,1.75) D4(-1.75,1.75) D12(2.25,1.75) D13(2.75,1.75) D14(3.25,1.75) E1(-3.25,1.25) E2(-2.75,1.25) E3(-2.25,1.25) E5(-1.25,1.25) E6(-0.75,1.25) E7(-0.25,1.25) E8(0.25,1.25) E9(0.75,1.25) E10(1.25,1.25) E12(2.25,1.25) E13(2.75,1.25) E14(3.25,1.25) F1(-3.25,0.75) F2(-2.75,0.75) F3(-2.25,0.75) F5(-1.25,0.75) F10(1.25,0.75) F12(2.25,0.75) F13(2.75,0.75) F14(3.25,0.75) G1(-3.25,0.25) G2(-2.75,0.25) G3(-2.25,0.25) G5(-1.25,0.25) G10(1.25,0.25) G12(2.25,0.25) G13(2.75,0.25) G14(3.25,0.25) H1(-3.25,-0.25) H2(-2.75,-0.25) H3(-2.25,-0.25) H5(-1.25,-0.25) H10(1.25,-0.25) H12(2.25,-0.25) H13(2.75,-0.25) H14(3.25,-0.25) J1(-3.25,-0.75) J2(-2.75,-0.75) J3(-2.25,-0.75) J5(-1.25,-0.75) J10(1.25,-0.75) J12(2.25,-0.75) J13(2.75,-0.75) J14(3.25,-0.75) K1(-3.25,-1.25) K2(-2.75,-1.25) K3(-2.25,-1.25) K5(-1.25,-1.25) K6(-0.75,-1.25) K7(-0.25,-1.25) K8(0.25,-1.25) K9(0.75,-1.25) K10(1.25,-1.25) K12(2.25,-1.25) K13(2.75,-1.25) K14(3.25,-1.25) L1(-3.25,-1.75) L2(-2.75,-1.75) L3(-2.25,-1.75) L12(2.25,-1.75) L13(2.75,-1.75) L14(3.25,-1.75) M1(-3.25,-2.25) M2(-2.75,-2.25) M3(-2.25,-2.25) M4(-1.75,-2.25) M5(-1.25,-2.25) M6(-0.75,-2.25) M7(-0.25,-2.25) M8(0.25,-2.25) M9(0.75,-2.25) M10(1.25,-2.25) M11(1.75,-2.25) M12(2.25,-2.25) M13(2.75,-2.25) M14(3.25,-2.25) N1(-3.25,-2.75) N2(-2.75,-2.75) N3(-2.25,-2.75) N4(-1.75,-2.75) N5(-1.25,-2.75) N6(-0.75,-2.75) N7(-0.25,-2.75) N8(0.25,-2.75) N9(0.75,-2.75) N10(1.25,-2.75) N11(1.75,-2.75) N12(2.25,-2.75) N13(2.75,-2.75) N14(3.25,-2.75) P1(-3.25,-3.25) P2(-2.75,-3.25) P3(-2.25,-3.25) P4(-1.75,-3.25) P5(-1.25,-3.25) P6(-0.75,-3.25) P7(-0.25,-3.25) P8(0.25,-3.25) P9(0.75,-3.25) P10(1.25,-3.25) P11(1.75,-3.25) P12(2.25,-3.25) P13(2.75,-3.25) P14(3.25,-3.25)
BGA232_0D65_T41
  round 0.3 smd: A1(-5.199,5.199) A2(-4.549,5.199) A3(-3.899,5.199) A5(-2.601,5.199) A7(-1.3,5.199) A9(0,5.199) A11(1.3,5.199) A13(2.601,5.199) A15(3.899,5.199) A16(4.549,5.199) A17(5.199,5.199) B1(-5.199,4.549) B2(-4.549,4.549) B3(-3.899,4.549) B4(-3.249,4.549) B5(-2.601,4.549) B6(-1.951,4.549) B7(-1.3,4.549) B8(-0.65,4.549) B9(0,4.549) B10(0.65,4.549) B11(1.3,4.549) B12(1.951,4.549) B13(2.601,4.549) B14(3.249,4.549) B15(3.899,4.549) B16(4.549,4.549) B17(5.199,4.549) C1(-5.199,3.899) C2(-4.549,3.899) C3(-3.899,3.899) C4(-3.249,3.899) C5(-2.601,3.899) C6(-1.951,3.899) C7(-1.3,3.899) C8(-0.65,3.899) C9(0,3.899) C10(0.65,3.899) C11(1.3,3.899) C12(1.951,3.899) C13(2.601,3.899) C14(3.249,3.899) C15(3.899,3.899) C16(4.549,3.899) C17(5.199,3.899) D2(-4.549,3.249) D3(-3.899,3.249) D4(-3.249,3.249) D9(0,3.249) D14(3.249,3.249) D15(3.899,3.249) D16(4.549,3.249) E1(-5.199,2.601) E2(-4.549,2.601) E3(-3.899,2.601) E5(-2.601,2.601) E6(-1.951,2.601) E7(-1.3,2.601) E8(-0.65,2.601) E9(0,2.601) E10(0.65,2.601) E11(1.3,2.601) E12(1.951,2.601) E15(3.899,2.601) E16(4.549,2.601) E17(5.199,2.601) F2(-4.549,1.951) F3(-3.899,1.951) F5(-2.601,1.951) F6(-1.951,1.951) F7(-1.3,1.951) F8(-0.65,1.951) F9(0,1.951) F10(0.65,1.951) F11(1.3,1.951) F12(1.951,1.951) F13(2.601,1.951) F15(3.899,1.951) F16(4.549,1.951) G1(-5.199,1.3) G2(-4.549,1.3) G3(-3.899,1.3) G5(-2.601,1.3) G6(-1.951,1.3) G7(-1.3,1.3) G8(-0.65,1.3) G9(0,1.3) G10(0.65,1.3) G11(1.3,1.3) G12(1.951,1.3) G13(2.601,1.3) G15(3.899,1.3) G16(4.549,1.3) G17(5.199,1.3) H2(-4.549,0.65) H3(-3.899,0.65) H5(-2.601,0.65) H6(-1.951,0.65) H7(-1.3,0.65) H8(-0.65,0.65) H9(0,0.65) H10(0.65,0.65) H11(1.3,0.65) H12(1.951,0.65) H13(2.601,0.65) H15(3.899,0.65) H16(4.549,0.65) J1(-5.199,0) J2(-4.549,0) J3(-3.899,0) J4(-3.249,0) J5(-2.601,0) J6(-1.951,0) J7(-1.3,0) J8(-0.65,0) J9(0,0) J10(0.65,0) J11(1.3,0) J12(1.951,0) J13(2.601,0) J14(3.249,0) J15(3.899,0) J16(4.549,0) J17(5.199,0) K2(-4.549,-0.65) K3(-3.899,-0.65) K5(-2.601,-0.65) K6(-1.951,-0.65) K7(-1.3,-0.65) K8(-0.65,-0.65) K9(0,-0.65) K10(0.65,-0.65) K11(1.3,-0.65) K12(1.951,-0.65) K13(2.601,-0.65) K15(3.899,-0.65) K16(4.549,-0.65) L1(-5.199,-1.3) L2(-4.549,-1.3) L3(-3.899,-1.3) L5(-2.601,-1.3) L6(-1.951,-1.3) L7(-1.3,-1.3) L8(-0.65,-1.3) L9(0,-1.3) L10(0.65,-1.3) L11(1.3,-1.3) L12(1.951,-1.3) L13(2.601,-1.3) L15(3.899,-1.3) L16(4.549,-1.3) L17(5.199,-1.3) M2(-4.549,-1.951) M3(-3.899,-1.951) M5(-2.601,-1.951) M6(-1.951,-1.951) M7(-1.3,-1.951) M8(-0.65,-1.951) M9(0,-1.951) M10(0.65,-1.951) M11(1.3,-1.951) M12(1.951,-1.951) M13(2.601,-1.951) M15(3.899,-1.951) M16(4.549,-1.951) N1(-5.199,-2.601) N2(-4.549,-2.601) N3(-3.899,-2.601) N5(-2.601,-2.601) N6(-1.951,-2.601) N7(-1.3,-2.601) N8(-0.65,-2.601) N9(0,-2.601) N10(0.65,-2.601) N11(1.3,-2.601) N12(1.951,-2.601) N13(2.601,-2.601) N15(3.899,-2.601) N16(4.549,-2.601) N17(5.199,-2.601) P2(-4.549,-3.249) P3(-3.899,-3.249) P4(-3.249,-3.249) P9(0,-3.249) P14(3.249,-3.249) P15(3.899,-3.249) P16(4.549,-3.249) R1(-5.199,-3.899) R2(-4.549,-3.899) R3(-3.899,-3.899) R4(-3.249,-3.899) R5(-2.601,-3.899) R6(-1.951,-3.899) R7(-1.3,-3.899) R8(-0.65,-3.899) R9(0,-3.899) R10(0.65,-3.899) R11(1.3,-3.899) R12(1.951,-3.899) R13(2.601,-3.899) R14(3.249,-3.899) R15(3.899,-3.899) R16(4.549,-3.899) R17(5.199,-3.899) T1(-5.199,-4.549) T2(-4.549,-4.549) T3(-3.899,-4.549) T4(-3.249,-4.549) T5(-2.601,-4.549) T6(-1.951,-4.549) T7(-1.3,-4.549) T8(-0.65,-4.549) T9(0,-4.549) T10(0.65,-4.549) T11(1.3,-4.549) T12(1.951,-4.549) T13(2.601,-4.549) T14(3.249,-4.549) T15(3.899,-4.549) T16(4.549,-4.549) T17(5.199,-4.549) U1(-5.199,-5.199) U2(-4.549,-5.199) U3(-3.899,-5.199) U5(-2.601,-5.199) U7(-1.3,-5.199) U9(0,-5.199) U11(1.3,-5.199) U13(2.601,-5.199) U15(3.899,-5.199) U16(4.549,-5.199) U17(5.199,-5.199)
C0402
  rect 0.45x0.549 smd: 1(-0.521,0) 2(0.521,0)
C0402_E
  rect 0.5x0.701 smd: 1(-0.546,0) 2(0.546,0)
C0603
  rect 0.759x0.759 smd: 1(-0.762,0) 2(0.762,0)
C1206
  rect 1.3x1.6 smd: 1(-1.4,0) 2(1.4,0)
CON2-1D25-LT
  rect 0.701x1.4 smd: 1(0.625,2.2) 2(-0.625,2.2)
  rect 1.9x2.4 smd: 3(-3.449,-0.549) 4(3.449,-0.549)
CON2-2D54-LC
  rect 1.524x1.524 hole 0.889: 1(-1.27,0)
  round 1.524 hole 0.889: 2(1.27,0)
CON4-1D0-WT
  rect 0.5x1.999 smd: 1(-1.501,2.499)
  oval 0.5x1.999 smd: 2(-0.5,2.499) 3(0.5,2.499) 4(1.501,2.499)
  rect 1.6x2.101 smd: 5(3,-1.501) 6(-3,-1.501)
CRY_2D5X2D0
  rect 1.001x0.899 smd: 1(-0.925,-0.775) 2(0.925,-0.775) 3(0.925,0.775) 4(-0.925,0.775)
CRY_3D2X1D5
  rect 1.001x1.801 smd: 1(-1.25,0) 2(1.25,0)
D0603_LED
  rect 0.8x0.8 smd: 1(-0.7,0) 2(0.7,0)
D0603_LED3_CC
  rect 0.8x0.65 smd: 1(-0.749,0.424) 2(0.749,0.424) 3(-0.749,-0.424) 4(0.749,-0.424)
DFN6_0D65_ETA3425
  rect 0.65x0.3 smd: 1(-1.026,0.65) 2(-1.026,0) 3(-1.026,-0.65) 4(1.026,-0.65) 5(1.026,0) 6(1.026,0.65)
  custom 0.17x0.17 smd: 7(0,0)
DFN16_0D5_ETA6003
  rect 0.701x0.249 smd: 1(-1.45,0.749) 2(-1.45,0.249) 3(-1.45,-0.249) 4(-1.45,-0.749) 9(1.45,-0.749) 10(1.45,-0.249) 11(1.45,0.249) 12(1.45,0.749)
  rect 0.249x0.701 smd: 5(-0.749,-1.45) 6(-0.249,-1.45) 7(0.249,-1.45) 8(0.749,-1.45) 13(0.749,1.45) 14(0.249,1.45) 15(-0.249,1.45) 16(-0.749,1.45)
  custom 0.413x0.413 smd: 17(0,0)
DFN1006
  rect 0.55x0.6 smd: 1(0.425,0) 2(-0.425,0)
DIP2_2D54_LED
  rect 1.199x1.199 hole 0.64: 1(-1.27,0)
  round 1.199 hole 0.64: 2(1.27,0)
DIP3_PIR
  round 1.199 hole 0.599: 1(-2.54,0) 2(0,-2.54) 3(2.54,0)
DIP4_P904B_S
  round 1.199 hole 0.64: 1(0,2.54) 2(-2.54,0) 3(0,-2.54) 4(2.54,0)
ESD0402
  rect 0.62x0.399 smd: 1(-0.541,0)
  rect 0.5x0.399 smd: 2(0.599,0)
FB0402
  rect 0.45x0.549 smd: 1(-0.549,0) 2(0.549,0)
FPC-CON30-0D5-LT
  rect 0.5x1.1 smd: 1(-7.249,-1.349) 2(-6.749,1.349) 3(-6.251,-1.349) 4(-5.751,1.349) 5(-5.25,-1.349) 6(-4.75,1.349) 7(-4.249,-1.349) 8(-3.749,1.349) 9(-3.249,-1.349) 10(-2.751,1.349) 11(-2.25,-1.349) 12(-1.75,1.349) 13(-1.25,-1.349) 14(-0.749,1.349) 15(-0.249,-1.349) 16(0.249,1.349) 17(0.749,-1.349) 18(1.25,1.349) 19(1.75,-1.349) 20(2.25,1.349) 21(2.751,-1.349) 22(3.249,1.349) 23(3.749,-1.349) 24(4.249,1.349) 25(4.75,-1.349) 26(5.25,1.349) 27(5.751,-1.349) 28(6.251,1.349) 29(6.749,-1.349) 30(7.249,1.349)
  rect 1.999x1.999 smd: 31(-9.54,0) 32(9.54,0)
FPC-CON36-0D5-LT
  rect 0.5x1.1 smd: 1(-8.75,-1.349) 2(-8.25,1.349) 3(-7.75,-1.349) 4(-7.249,1.349) 5(-6.749,-1.349) 6(-6.251,1.349) 7(-5.751,-1.349) 8(-5.25,1.349) 9(-4.75,-1.349) 10(-4.249,1.349) 11(-3.749,-1.349) 12(-3.249,1.349) 13(-2.751,-1.349) 14(-2.25,1.349) 15(-1.75,-1.349) 16(-1.25,1.349) 17(-0.749,-1.349) 18(-0.249,1.349) 19(0.249,-1.349) 20(0.749,1.349) 21(1.25,-1.349) 22(1.75,1.349) 23(2.25,-1.349) 24(2.751,1.349) 25(3.249,-1.349) 26(3.749,1.349) 27(4.249,-1.349) 28(4.75,1.349) 29(5.25,-1.349) 30(5.751,1.349) 31(6.251,-1.349) 32(6.749,1.349) 33(7.249,-1.349) 34(7.75,1.349) 35(8.25,-1.349) 36(8.75,1.349)
  rect 1.999x1.999 smd: 37(-11.039,0) 38(11.039,0)
HEADER7X2M_2D54
  rect 1.501x1.501 hole 0.899: 1(-7.62,1.27)
  round 1.501 hole 0.899: 2(-7.62,-1.27) 3(-5.08,1.27) 4(-5.08,-1.27) 5(-2.54,1.27) 6(-2.54,-1.27) 7(0,1.27) 8(0,-1.27) 9(2.54,1.27) 10(2.54,-1.27) 11(5.08,1.27) 12(5.08,-1.27) 13(7.62,1.27) 14(7.62,-1.27)
HEADER9X2M_1D27
  rect 0.899x0.899 hole 0.5: 1(5.08,0.635)
  round 0.899 hole 0.5: 2(5.08,-0.635) 3(3.81,0.635) 4(3.81,-0.635) 5(2.54,0.635) 6(2.54,-0.635) 7(1.27,0.635) 8(1.27,-0.635) 9(0,0.635) 10(0,-0.635) 11(-1.27,0.635) 12(-1.27,-0.635) 13(-2.54,0.635) 14(-2.54,-0.635) 15(-3.81,0.635) 16(-3.81,-0.635) 17(-5.08,0.635) 18(-5.08,-0.635)
L2016
  rect 0.851x1.699 smd: 1(0.899,0) 2(-0.899,0)
L2520
  rect 0.851x1.999 smd: 1(-1.151,0) 2(1.151,0)
LCD_CON37_0D5_WTXG_MTF28
  rect 0.3x1.801 smd: 1(9,3) 2(8.5,3) 3(8,3) 4(7.5,3) 5(7,3) 6(6.5,3) 7(6,3) 8(5.5,3) 9(5,3) 10(4.5,3) 11(4,3) 12(3.5,3) 13(3,3) 14(2.5,3) 15(2,3) 16(1.5,3) 17(1,3) 18(0.5,3) 19(0,3) 20(-0.5,3) 21(-1,3) 22(-1.5,3) 23(-2,3) 24(-2.5,3) 25(-3,3) 26(-3.5,3) 27(-4,3) 28(-4.5,3) 29(-5,3) 30(-5.5,3) 31(-6,3) 32(-6.5,3) 33(-7,3) 34(-7.5,3) 35(-8,3) 36(-8.5,3) 37(-9,3)
  rect 1.801x2.2 smd: 38(-10.65,-0.15) 39(10.65,-0.15)
MHOLE_3D0X2D0
  oval 4.201x3.2 hole 3x1.999 rot 45: 1(0,0)
MHOLE_5D5P3D2H
  round 5.499 hole 3.2: 1(0,0)
  round 0.599 hole 0.399: 2(-2.2,0) 3(-1.554,-1.554) 4(0,-2.2) 5(1.554,-1.554) 6(2.2,0) 7(1.554,1.554) 8(0,2.2) 9(-1.554,1.554)
MICROUSB_B_NJ5P
  rect 0.399x1.349 smd: 1(1.3,0) 2(0.65,0) 3(0,0) 4(-0.65,0) 5(-1.3,0)
  rect 1.4x1.999 hole 0.5x1.199: 6(3.625,2.626) 7(-3.625,2.626)
  oval 1.1x1.349 hole 0.599: 8(-2.426,-0.124) 9(2.426,-0.124)
  rect 1.199x1.501 smd: 10(-0.8,2.626) 11(0.8,2.626)
MSOP8_0D65
  oval 0.351x1.501 smd: 1(-0.975,-2.301) 2(-0.325,-2.301) 3(0.325,-2.301) 4(0.975,-2.301) 5(0.975,2.301) 6(0.325,2.301) 7(-0.325,2.301) 8(-0.975,2.301)
PD2_2D54
  rect 1.199x1.199 hole 0.64: 1(1.27,0)
  round 1.199 hole 0.64: 2(-1.27,0)
PSW_3P
  round 2.54 hole 1.781: 1(0,4.445) 2(0,0) 3(0,-4.445)
QFN8_0D5_CW2015
  rect 0.3x0.8 smd: 1(-0.749,-1.476) 2(-0.249,-1.476) 3(0.249,-1.476) 4(0.749,-1.476) 5(0.749,1.476) 6(0.249,1.476) 7(-0.249,1.476) 8(-0.749,1.476)
  custom 0.375x0.375 smd: 9(0,0)
QFN32_0D5_SZ18201
  rect 0.701x0.249 smd: 1(-2.451,1.75) 2(-2.451,1.25) 3(-2.451,0.749) 4(-2.451,0.249) 5(-2.451,-0.249) 6(-2.451,-0.749) 7(-2.451,-1.25) 8(-2.451,-1.75) 17(2.451,-1.75) 18(2.451,-1.25) 19(2.451,-0.749) 20(2.451,-0.249) 21(2.451,0.249) 22(2.451,0.749) 23(2.451,1.25) 24(2.451,1.75)
  rect 0.249x0.701 smd: 9(-1.75,-2.451) 10(-1.25,-2.451) 11(-0.749,-2.451) 12(-0.249,-2.451) 13(0.249,-2.451) 14(0.749,-2.451) 15(1.25,-2.451) 16(1.75,-2.451) 25(1.75,2.451) 26(1.25,2.451) 27(0.749,2.451) 28(0.249,2.451) 29(-0.249,2.451) 30(-0.749,2.451) 31(-1.25,2.451) 32(-1.75,2.451)
  custom 0.85x0.85 smd: 33(0,0)
QFP16_1D27
  rect 1.4x0.5 smd: 1(-4.6,4.445) 2(-4.6,3.175) 3(-4.6,1.905) 4(-4.6,0.635) 5(-4.6,-0.635) 6(-4.6,-1.905) 7(-4.6,-3.175) 8(-4.6,-4.445) 9(4.6,-4.445) 10(4.6,-3.175) 11(4.6,-1.905) 12(4.6,-0.635) 13(4.6,0.635) 14(4.6,1.905) 15(4.6,3.175) 16(4.6,4.445)
R0402
  rect 0.45x0.549 smd: 1(-0.521,0) 2(0.521,0)
R0603
  rect 0.759x0.759 smd: 1(-0.762,0) 2(0.762,0)
R1206
  rect 1.3x1.6 smd: 1(-1.4,0) 2(1.4,0)
RJ45-LED-1A
  round 3.249 hole 3.249 unplated: (-6.35,5.136) (6.35,5.136)
  rect 1.27x1.27 hole 0.889: 1(3.579,7.676)
  round 1.27 hole 0.889: 2(2.56,9.451) 3(1.539,7.676) 4(0.521,9.451) 5(-0.5,7.676) 6(-1.519,9.451) 7(-2.54,7.676) 8(-3.561,9.451) 11(-6.861,14.27) 12(-4.569,14.27) 13(4.569,14.27) 14(6.861,14.27)
  round 2.286 hole 1.524: 9(-8.131,8.565) 10(8.131,8.565)
SIP2M_2D54
  rect 1.524x1.524 hole 0.889: 1(-1.27,0)
  round 1.524 hole 0.889: 2(1.27,0)
SMB
  rect 1.999x2.799 smd: 1(2.499,0) 2(-2.499,0)
SOD923_RB521CS-30
  rect 0.65x0.549 smd: 1(-0.475,0) 2(0.475,0)
SOP8_1D27_BM8563
  rect 0.399x1.501 smd: 1(-1.905,-2.7) 2(-0.635,-2.7) 3(0.635,-2.7) 4(1.905,-2.7) 5(1.905,2.7) 6(0.635,2.7) 7(-0.635,2.7) 8(-1.905,2.7)
SOT23
  rect 0.8x1.1 smd: 1(-0.95,-1.349) 2(0.95,-1.349) 3(0,1.349)
SOT23-5
  rect 0.599x1.501 smd: 1(-0.95,-1.501) 2(0,-1.501) 3(0.95,-1.501) 4(0.95,1.501) 5(-0.95,1.501)
SOT563
  rect 0.249x0.599 smd: 1(-0.5,-0.701) 2(0,-0.701) 3(0.5,-0.701) 4(0.5,0.701) 5(0,0.701) 6(-0.5,0.701)
SW2_SMD
  rect 2.5x1.5 smd: 1(-3.5,0) 2(3.5,0)
TEST_HOLE
  round 1.778 hole 0.889: 1(0,0)
TEST_SMD
  round 1.001 smd: 1(0,0)
TEST_SMD_0D5
  round 0.5 smd: 1(0,0)
TFCARD
  round 1.001 hole 1.001 unplated: (-4.95,-10.599) (3.051,-10.599)
  rect 0.701x1.801 smd: 1(2.25,0.201) 2(1.151,0.201) 3(0.051,0.201) 4(-1.049,0.201) 5(-2.149,0.201) 6(-3.249,0.201) 7(-4.351,0.201) 8(-5.451,0.201) 9(-6.551,0.201)
  rect 1.6x1.4 smd: 10(-8.001,-0.599) 13(6.85,-0.599)
  rect 1.199x2.2 smd: 11(-7.75,-10.201) 12(7.75,-10.201)
TQFN16_0D5_SGM3124
  rect 0.701x0.231 smd: 1(-1.45,0.75) 2(-1.45,0.25) 3(-1.45,-0.25) 4(-1.45,-0.75) 9(1.45,-0.75) 10(1.45,-0.25) 11(1.45,0.25) 12(1.45,0.75)
  rect 0.231x0.701 smd: 5(-0.75,-1.45) 6(-0.25,-1.45) 7(0.25,-1.45) 8(0.75,-1.45) 13(0.75,1.45) 14(0.25,1.45) 15(-0.25,1.45) 16(-0.75,1.45)
  rect 1.501x1.501 smd: 17(0,0)
TSSOP14_0D65_SGM8044
  rect 1.801x0.399 smd: 1(-2.969,1.951) 2(-2.969,1.3) 3(-2.969,0.65) 4(-2.969,0) 5(-2.969,-0.65) 6(-2.969,-1.3) 7(-2.969,-1.951) 8(2.969,-1.951) 9(2.969,-1.3) 10(2.969,-0.65) 11(2.969,0) 12(2.969,0.65) 13(2.969,1.3) 14(2.969,1.951)
WSOP8_1D27
  rect 1.9x0.5 smd: 1(-3.645,1.905) 2(-3.645,0.635) 3(-3.645,-0.635) 4(-3.645,-1.905) 5(3.645,-1.905) 6(3.645,-0.635) 7(3.645,0.635) 8(3.645,1.905)

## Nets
1V8: C22.1 C23.1 C25.1 L4.2 R20.2 R23.2 R55.2 R139.2 TP7.1 U4.6(OUT)
3V3: C18.1 C19.1 C24.1 C70.2 C80.1 C81.1 C82.1 C101.1 C102.1 C116.1 C117.1 C120.1 C148.2 FB1.1 FB11.1 L3.2 Q3.2(SOURCE) Q4.1(BASE) Q8.2(SOURCE) R19.2 R25.2 R44.2 R57.2 R66.1 R88.2 R89.2 R98.2 R99.2 R112.2 R123.2 R129.1 R140.2 R147.1 R148.1 R151.1 R152.2 R153.2 R157.2 R165.2 R189.1 R192.1 R196.1 R199.1 R202.1 R205.1 R207.1 R210.2 R270.2 R271.2 TP6.1 U3.6(OUT) U8.8(VCC) U18.8(VCC) U19.14(DVDD33_1)
AVDD33: C152.1 C153.1 R209.2 R210.1 U19.7(AVDD33_1)
GND: BT1.2(-) C1.2 C2.2 C3.2 C4.2 C5.2 C6.2 C7.2 C8.2 C9.2 C10.2 C11.2 C12.2 C13.2 C14.2 C16.2 C17.2 C18.2 C19.2 C20.2 C21.2 C22.2 C23.2 C26.2 C27.2 C28.2 C29.2 C30.2 C31.2 C32.2 C33.2 C36.2 C37.2 C38.2 C39.2 C40.2 C41.2 C43.2 C44.2 C45.2 C46.2 C47.2 C48.2 C49.2 C50.2 C51.2 C52.2 C53.2 C54.2 C55.2 C56.2 C57.2 C58.2 C59.2 C60.2 C61.2 C62.2 C63.2 C66.1 C67.1 C68.2 C69.2 C70.1 C71.1 C72.1 C73.2 C74.2 C75.2 C77.2 C80.2 C81.2 C83.2 C84.2 C85.2 C86.2 C87.2 C88.2 C89.2 C90.2 C91.2 C92.2 C93.2 C94.2 C95.1 C96.2 C97.2 C98.2 C99.2 C100.2 C101.2 C103.2 C104.2 C105.2 C106.2 C107.2 C108.2 C109.2 C110.2 C111.2 C112.2 C113.2 C114.2 C116.2 C117.2 C118.2 C119.2 C120.2 C121.2 C122.2 C123.2 C124.2 C125.2 C126.2 C127.2 C128.2 C129.2 C130.2 C131.2 C132.2 C133.2 C134.2 C135.2 C136.2 C137.2 C138.2 C139.2 C140.2 C141.2 C142.2 C143.2 C144.2 C145.2 C146.2 C147.2 C148.1 C149.2 C150.2 C151.2 C152.2 C153.2 C154.1 C155.1 C156.1 C157.1 C158.1 C159.1 C164.2 C165.2 C166.2 C167.2 C168.2 C169.2 C170.2 C171.2 C172.2 C173.2 C174.2 C175.2 C176.2 C177.2 C179.2 C180.2 C181.2 C184.1 C185.1 C187.2 C188.2 C189.2 C190.2 C191.2 C192.2 C193.2 C194.2 C196.2 C198.2 C201.2 C202.2 C203.2 C204.2 C205.2 C206.2 D1.1(ANODE) D2.1(ANODE) D3.1(ANODE) D4.1(ANODE) D5.1(ANODE) D6.1(ANODE) D7.1(ANODE) D8.1(ANODE) D9.1(ANODE) D10.1(ANODE) D11.4(CATHODE) D13.2(CATHODE) D15.1(ANODE) D17.2 H1.1(A) H2.1(A) H3.1(A) J2.5(GND1) J2.6(GND2) J2.7(GND3) J2.8(GND4) J2.9(GND5) J2.10(GND6) J2.11(GND7) J3.2 J4.2 J4.5(S1) J4.6(S2) J5.3(S1) J5.4(S2) J6.6(VSS2) J6.10(GND_2) J6.11(GND_1) J6.12(PAD1) J6.13(PAD2) J7.3(S1) J7.4(S2) J9.3 J9.4 J9.8 J9.9 J9.12 J9.13 J9.15 J9.16 J10.7 J10.10 J10.15 J10.20 J10.27 J10.29 J10.37(S1) J10.38(S2) J11.1 J11.4 J11.7 J11.10 J11.13 J11.16 J11.21 J11.23 J11.27 J11.31(S1) J11.32(S2) J12.4 J12.13 J12.14 J13.9(SH1) J13.10(SH2) J13.12(CON_PIN[11]) J13.14(CON_PIN[13]) J14.9 J14.10 J14.15 J14.18 J15.1(DB1) J15.2(DB2) J15.3(DB3) J15.4(DB4) J15.5(GND1) J15.22(DB5) J15.34(GND2) J15.35(DB6) J15.36(DB7) J15.37(DB8) J15.38(G1) J15.39(G2) Q2.2(EMITTER) R1.1 R3.1 R5.2 R6.1 R7.1 R11.1 R12.1 R17.1 R27.2 R28.1 R29.1 R36.1 R37.1 R53.2 R58.2 R67.2 R68.2 R91.2 R115.1 R116.1 R117.1 R119.1 R120.1 R122.1 R159.2 R167.2 R193.2 R194.2 R197.2 R200.2 R201.1 R203.2 R204.1 R206.2 R212.2 R214.2 R226.1 R232.1 R233.2 R259.1 R262.1 R266.1 R267.1 R268.1 R269.1 R272.1 SW1.1 SW2.2 SW3.1 T1.1 T1.2 T1.3 T1.4 T1.5 T1.6 T1.7 T1.8 T1.9 T2.1 T2.2 T2.3 T2.4 T2.5 T2.6 T2.7 T2.8 T2.9 T3.1 T3.2 T3.3 T3.4 T3.5 T3.6 T3.7 T3.8 T3.9 T4.1 T4.2 T4.3 T4.4 T4.5 T4.6 T4.7 T4.8 T4.9 U1.5(PGND) U1.6(ENB) U1.8(ENPPB) U1.10(GND) U1.17(EPAD) U2.6(GND_0) U2.7(GND_1) U3.2(GND) U4.2(GND) U5.2(GND) U6.6(GND_0) U6.7(GND_1) U7.C9(DDRPLL_VSSA) U7.G5(PLL_AVSS) U7.G6(VSS1) U7.G7(VSS2) U7.G8(VSS3) U7.G9(VSS4) U7.G10(VSS5) U7.G11(VSS6) U7.G12(VSS7) U7.G13(VSS8) U7.J6(VSS9) U7.J7(VSS10) U7.J8(VSS11) U7.J9(VSS12) U7.J10(VSS13) U7.J11(VSS14) U7.J12(VSS15) U7.K6(VSS16) U7.K7(VSS17) U7.K8(VSS18) U7.K9(VSS19) U7.K10(VSS20) U7.K11(VSS21) U7.K12(VSS22) U7.L6(VSS23) U7.L7(VSS24) U7.L8(VSS25) U7.L9(VSS26) U7.L10(VSS27) U7.L11(VSS28) U7.L12(VSS29) U7.M7(VSS30) U7.M8(VSS31) U7.M9(VSS32) U7.M10(VSS33) U7.M11(VSS34) U7.M12(VSS35) U7.M13(VSS36) U7.N5(CSI_VSSA) U7.N12(VSS37) U7.N13(SADC_AGND) U7.P4(CODEC_AVSS) U8.4(GND) U9.1(CTG) U9.4(GND) U10.7(GND) U11.A6(VSS_1) U11.C4(VSSQ_1) U11.E7(VSS_2) U11.G5(VSS_3) U11.H10(VSS_4) U11.J5(VSS_5) U11.K8(VSS_6) U11.N2(VSSQ_2) U11.N5(VSSQ_3) U11.P4(VSSQ_4) U11.P6(VSSQ_5) U12.2(GND) U13.2(GND) U14.2(GND) U15.2(GND) U16.3(GND) U18.4(GND) U19.33(GND) U21.4(GND) U23.7(PGND) U23.14(GND) U23.17(POWER_PAD) U24.11 U25.1(VSS) Y1.2 Y1.4
VBAT2: BT1.1(+) C8.1 R2.2 R49.2 R50.2 U1.14(BATT_0) U1.16(BATT_1)
VCC_3V3: C12.1 C13.1 C14.1 C86.1 C166.1 C167.1 C168.1 C181.1 L2.2 L8.2 R13.2 R16.2 R54.2 R93.2 R96.2 R97.1 R141.1 R234.1 TP35.1 U12.1(VIN) U21.8(VDD)
VCC_5V: C2.1 C6.1 C7.1 C184.2 D3.2(CATHODE) J2.1(VBUS) R4.2 R9.2 R10.2 R24.2 TP1.1 U1.2(IN) U23.13(VIN)
VCC_IN: C3.1 C4.1 J1.1 L1.2 U1.1(SYS_0) U1.15(SYS_1)
VCC_SOC: C16.1 C17.1 C20.1 C21.1 C26.1 C27.1 C30.1 C31.1 C109.1 C110.1 J12.1 J12.2 Q1.3(DRAIN) R22.1 R26.1 R32.1 R34.1 R56.2 R127.2 R128.1 TP5.1 U3.3(VIN) U4.3(VIN) U5.3(VIN) U14.3(VIN)
VCC_SYS: C1.1 J1.2 R14.1 R18.1 R111.1 R173.1 TP2.1
VCCQ_3V3: C89.1 C90.1 FB11.2 R70.1 R71.1 R72.1 R73.1 R74.1 R75.1 R76.1 R77.1 R78.1 R79.2 U11.C6(VCCQ_5) U11.M4(VCCQ_1) U11.N4(VCCQ_2) U11.P3(VCCQ_3) U11.P5(VCCQ_4)
VDD_TFT: C103.1 C104.1 J15.6(VDD1) R151.2
VDDIO2: C172.1 C173.1 R138.2 R185.2 U7.C4(VDDIO2)
VDDMSC0: C83.1 C84.1 D8.2(CATHODE) J6.4(VDD) Q3.3(DRAIN) R61.1 R62.1 R63.1 R64.1 R65.1 R68.1
ADC_AVDD: C73.1 C74.1 FB7.2 U7.N16(SADC_VREFP) U7.N17(SADC_AVDD)
ALS_MEASURE_EN_PB22: R112.1 R114.2 U7.D15(MSC1_D3_PB22)
BAT_ADC_IOT: C5.1 J14.14 R2.1 R3.2
BAT_ALRT_N_IOT: J14.3 R47.2 U9.5(A\L\R\T\)
BOOTSEL0: R270.1 SW3.2 U7.A9(BOOT_SEL0_PC00)
BOOTSEL1: R271.1 R272.2 U7.B9(BOOT_SEL1_PC01)
BT656_D0_PD00: J12.5 R144.2
BT656_D1_PD01: J12.6 R146.2
BT656_D2_PD02: J12.7 R150.2
BT656_D3_PD03: J12.8 R155.2
BT656_D4_PD04: J12.9 R158.2
BT656_D5_PD05: J12.10 R161.2
BT656_D6_PD06: J12.11 R163.2
BT656_D7_PD07: J12.12 R166.2
BT656_PCLK_PD08: J12.3 R169.2
BT_UART0_CTS_PC11: R218.1 U7.C5(I2S_DAC_MCLK_PC11)
BT_UART0_RTS_PC12: R223.1 U7.A5(I2S_ADC_MCLK_PC12)
BT_UART0_RXD_PC09: R213.1 U7.C6(SMB2_SCK_PC09)
BT_UART0_TXD_PC08: R187.1 U7.B6(SMB2_SDA_PC08)
